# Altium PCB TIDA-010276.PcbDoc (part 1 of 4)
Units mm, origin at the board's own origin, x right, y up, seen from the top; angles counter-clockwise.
Board outline 146.48 x 90.27 mm, 4 copper layers (Top Layer, Signal Layer1, Signal Layer2, Bottom Layer), stack 1.631 mm thick; 271 components, 98 nets, 671 pads, 1828 vias.
Unrouted connection lines stored in the file: 2.
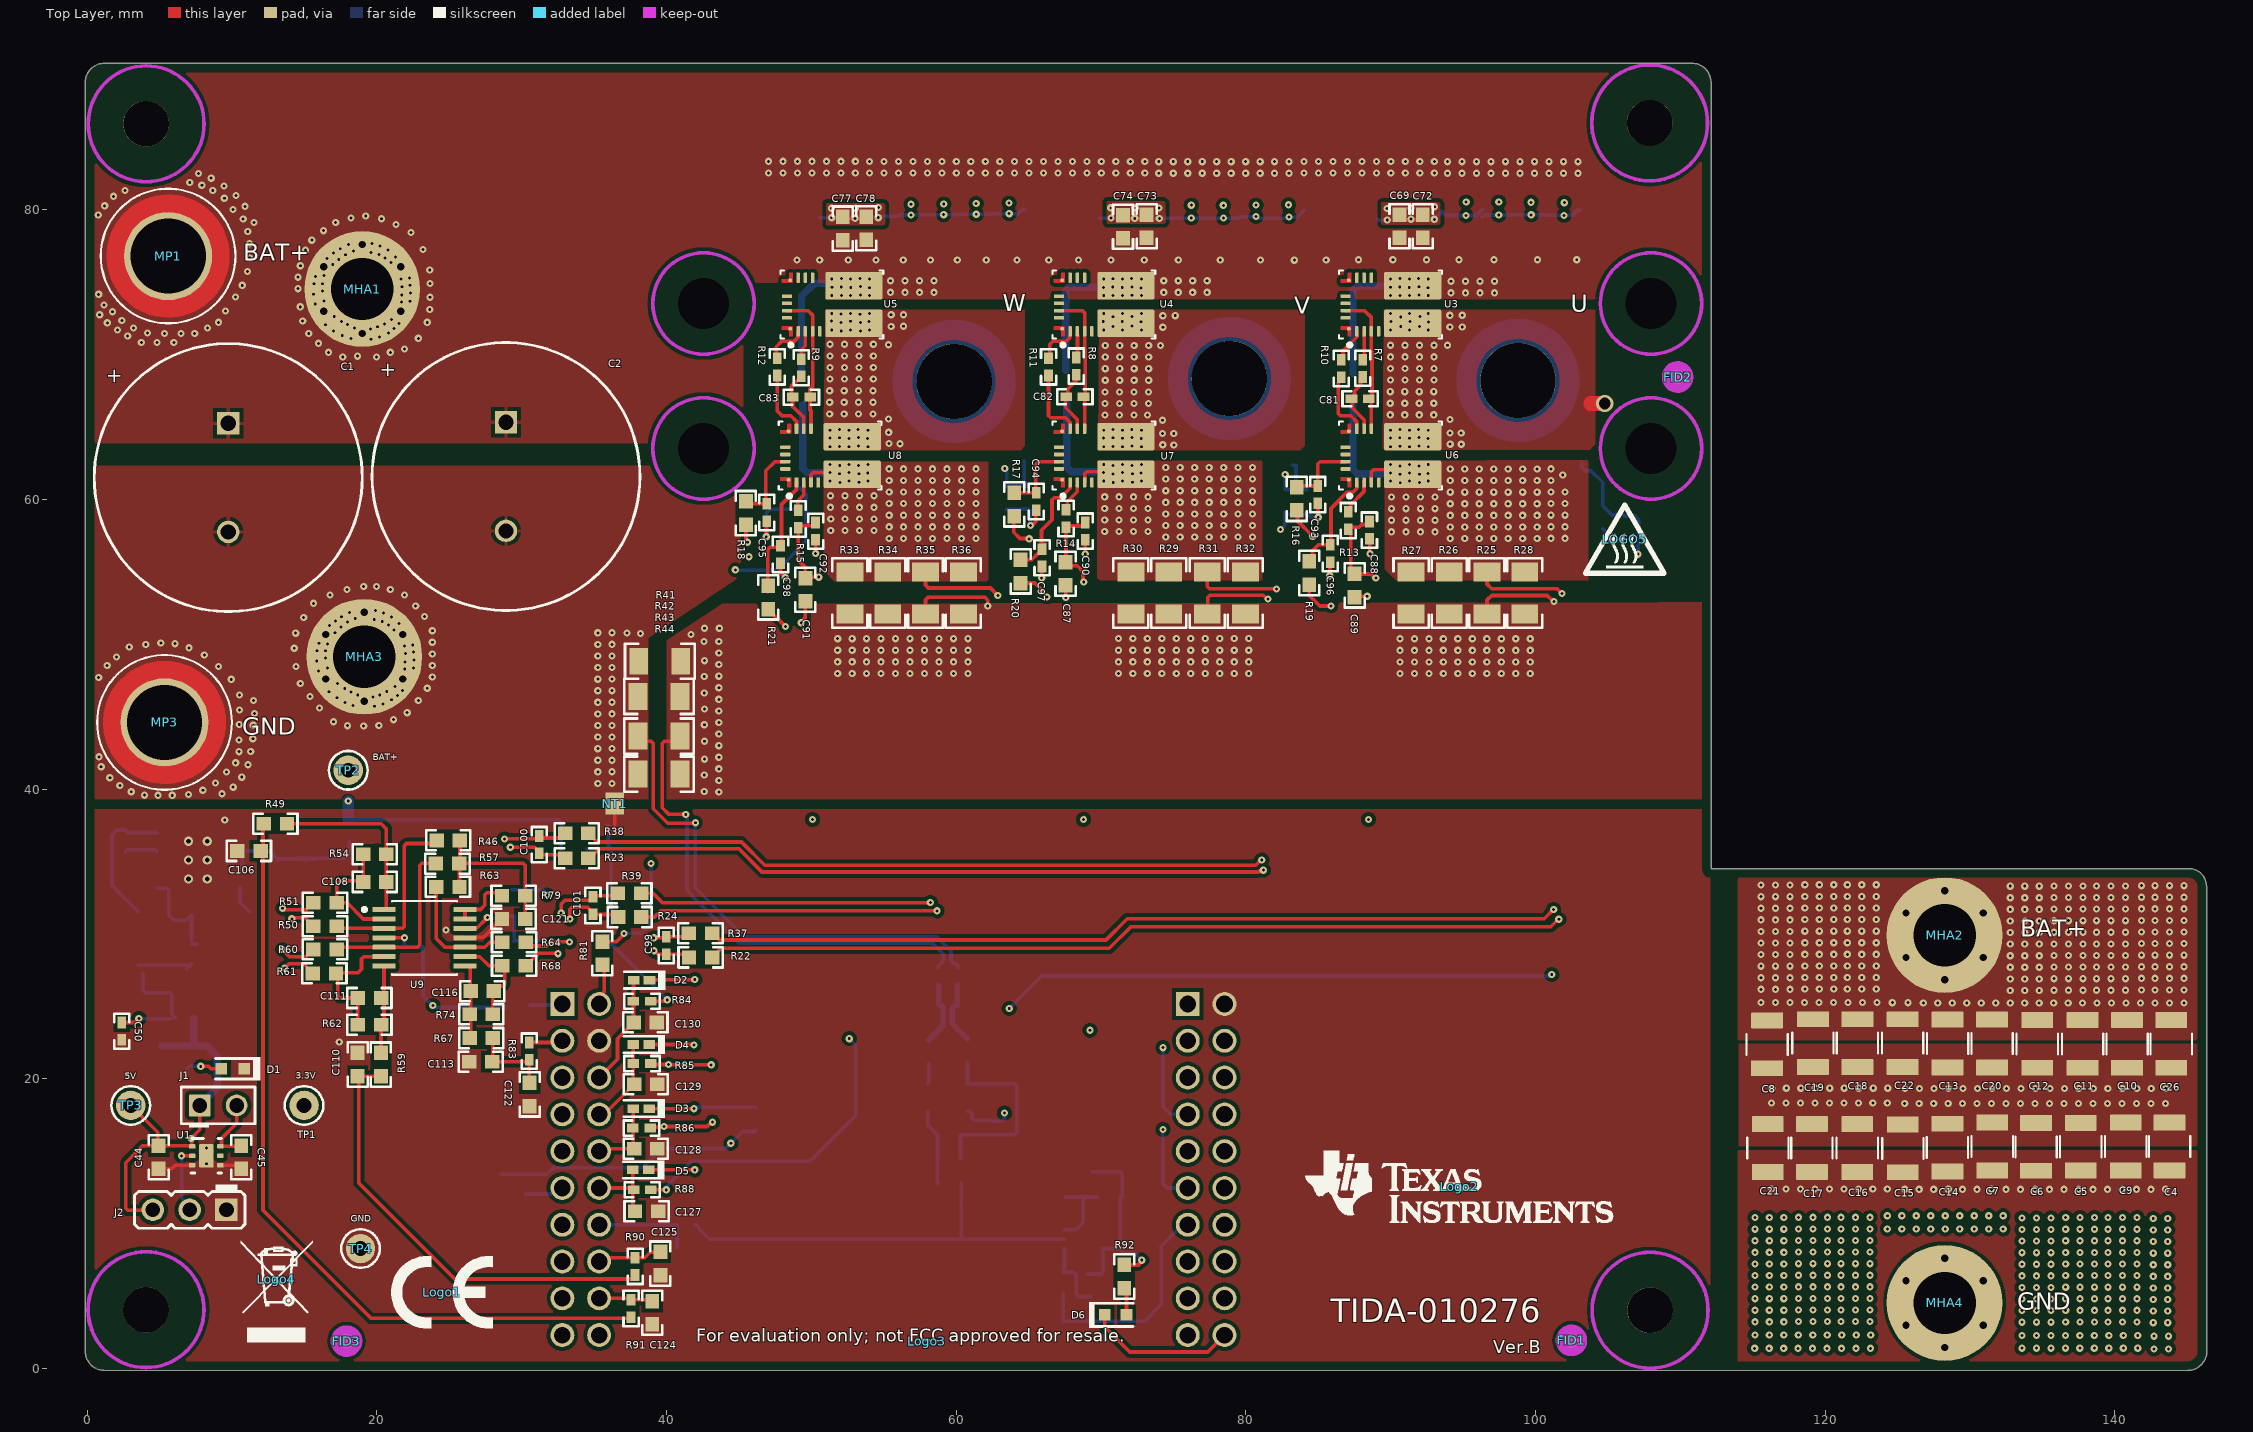
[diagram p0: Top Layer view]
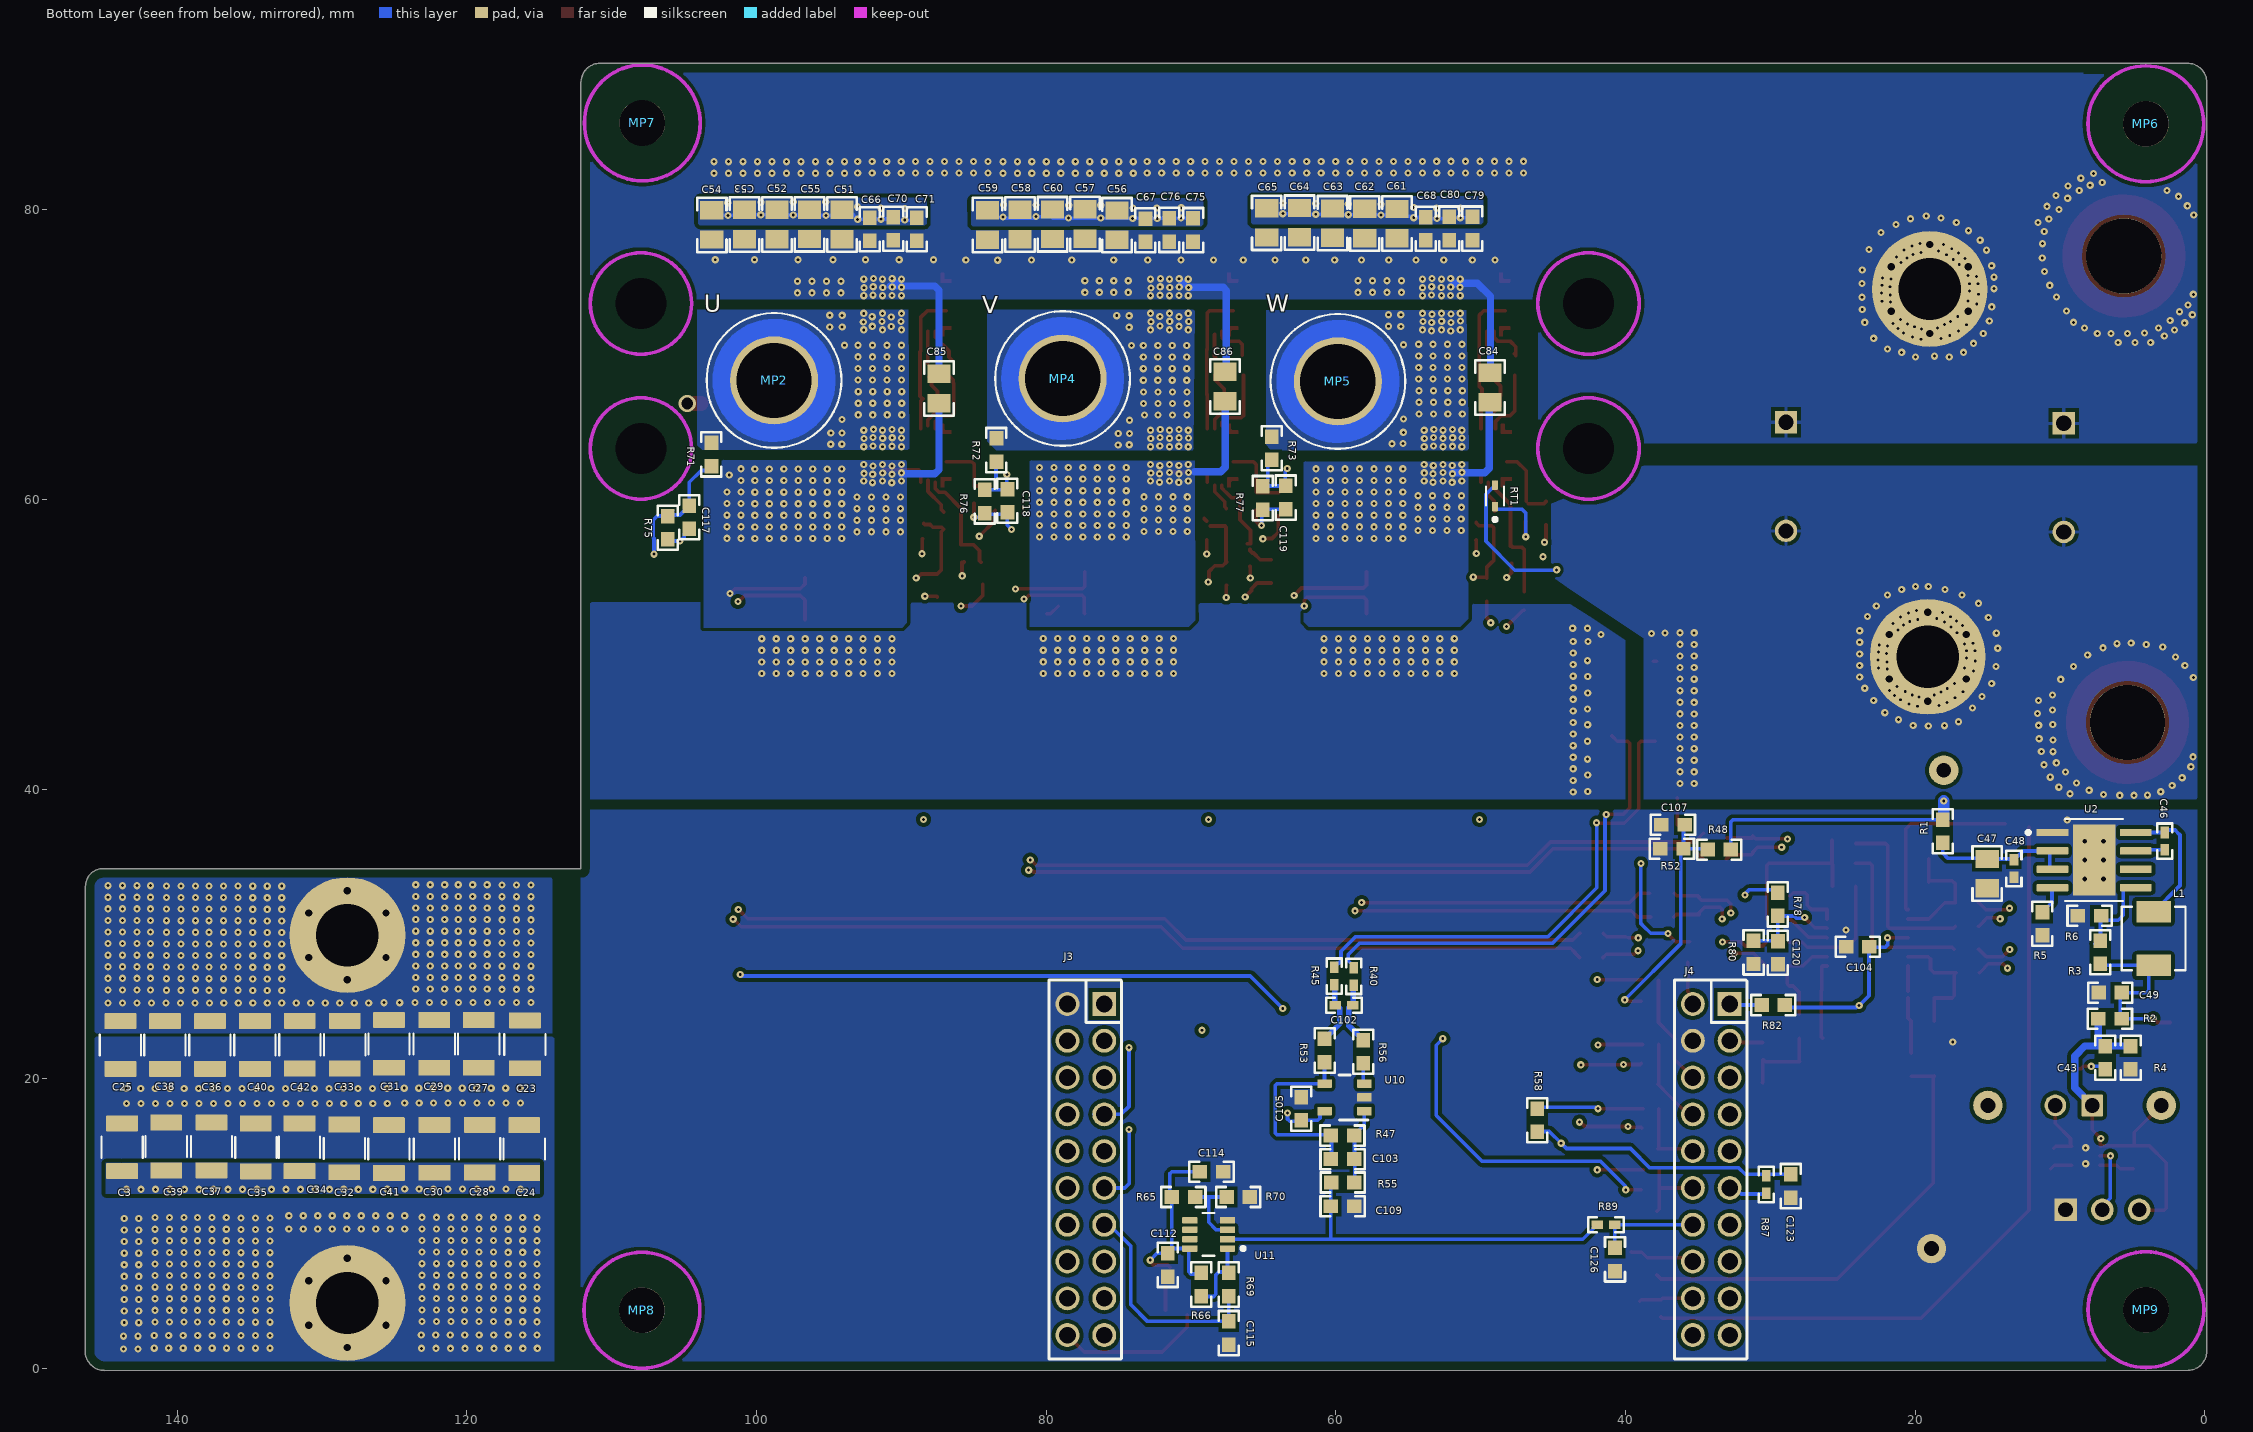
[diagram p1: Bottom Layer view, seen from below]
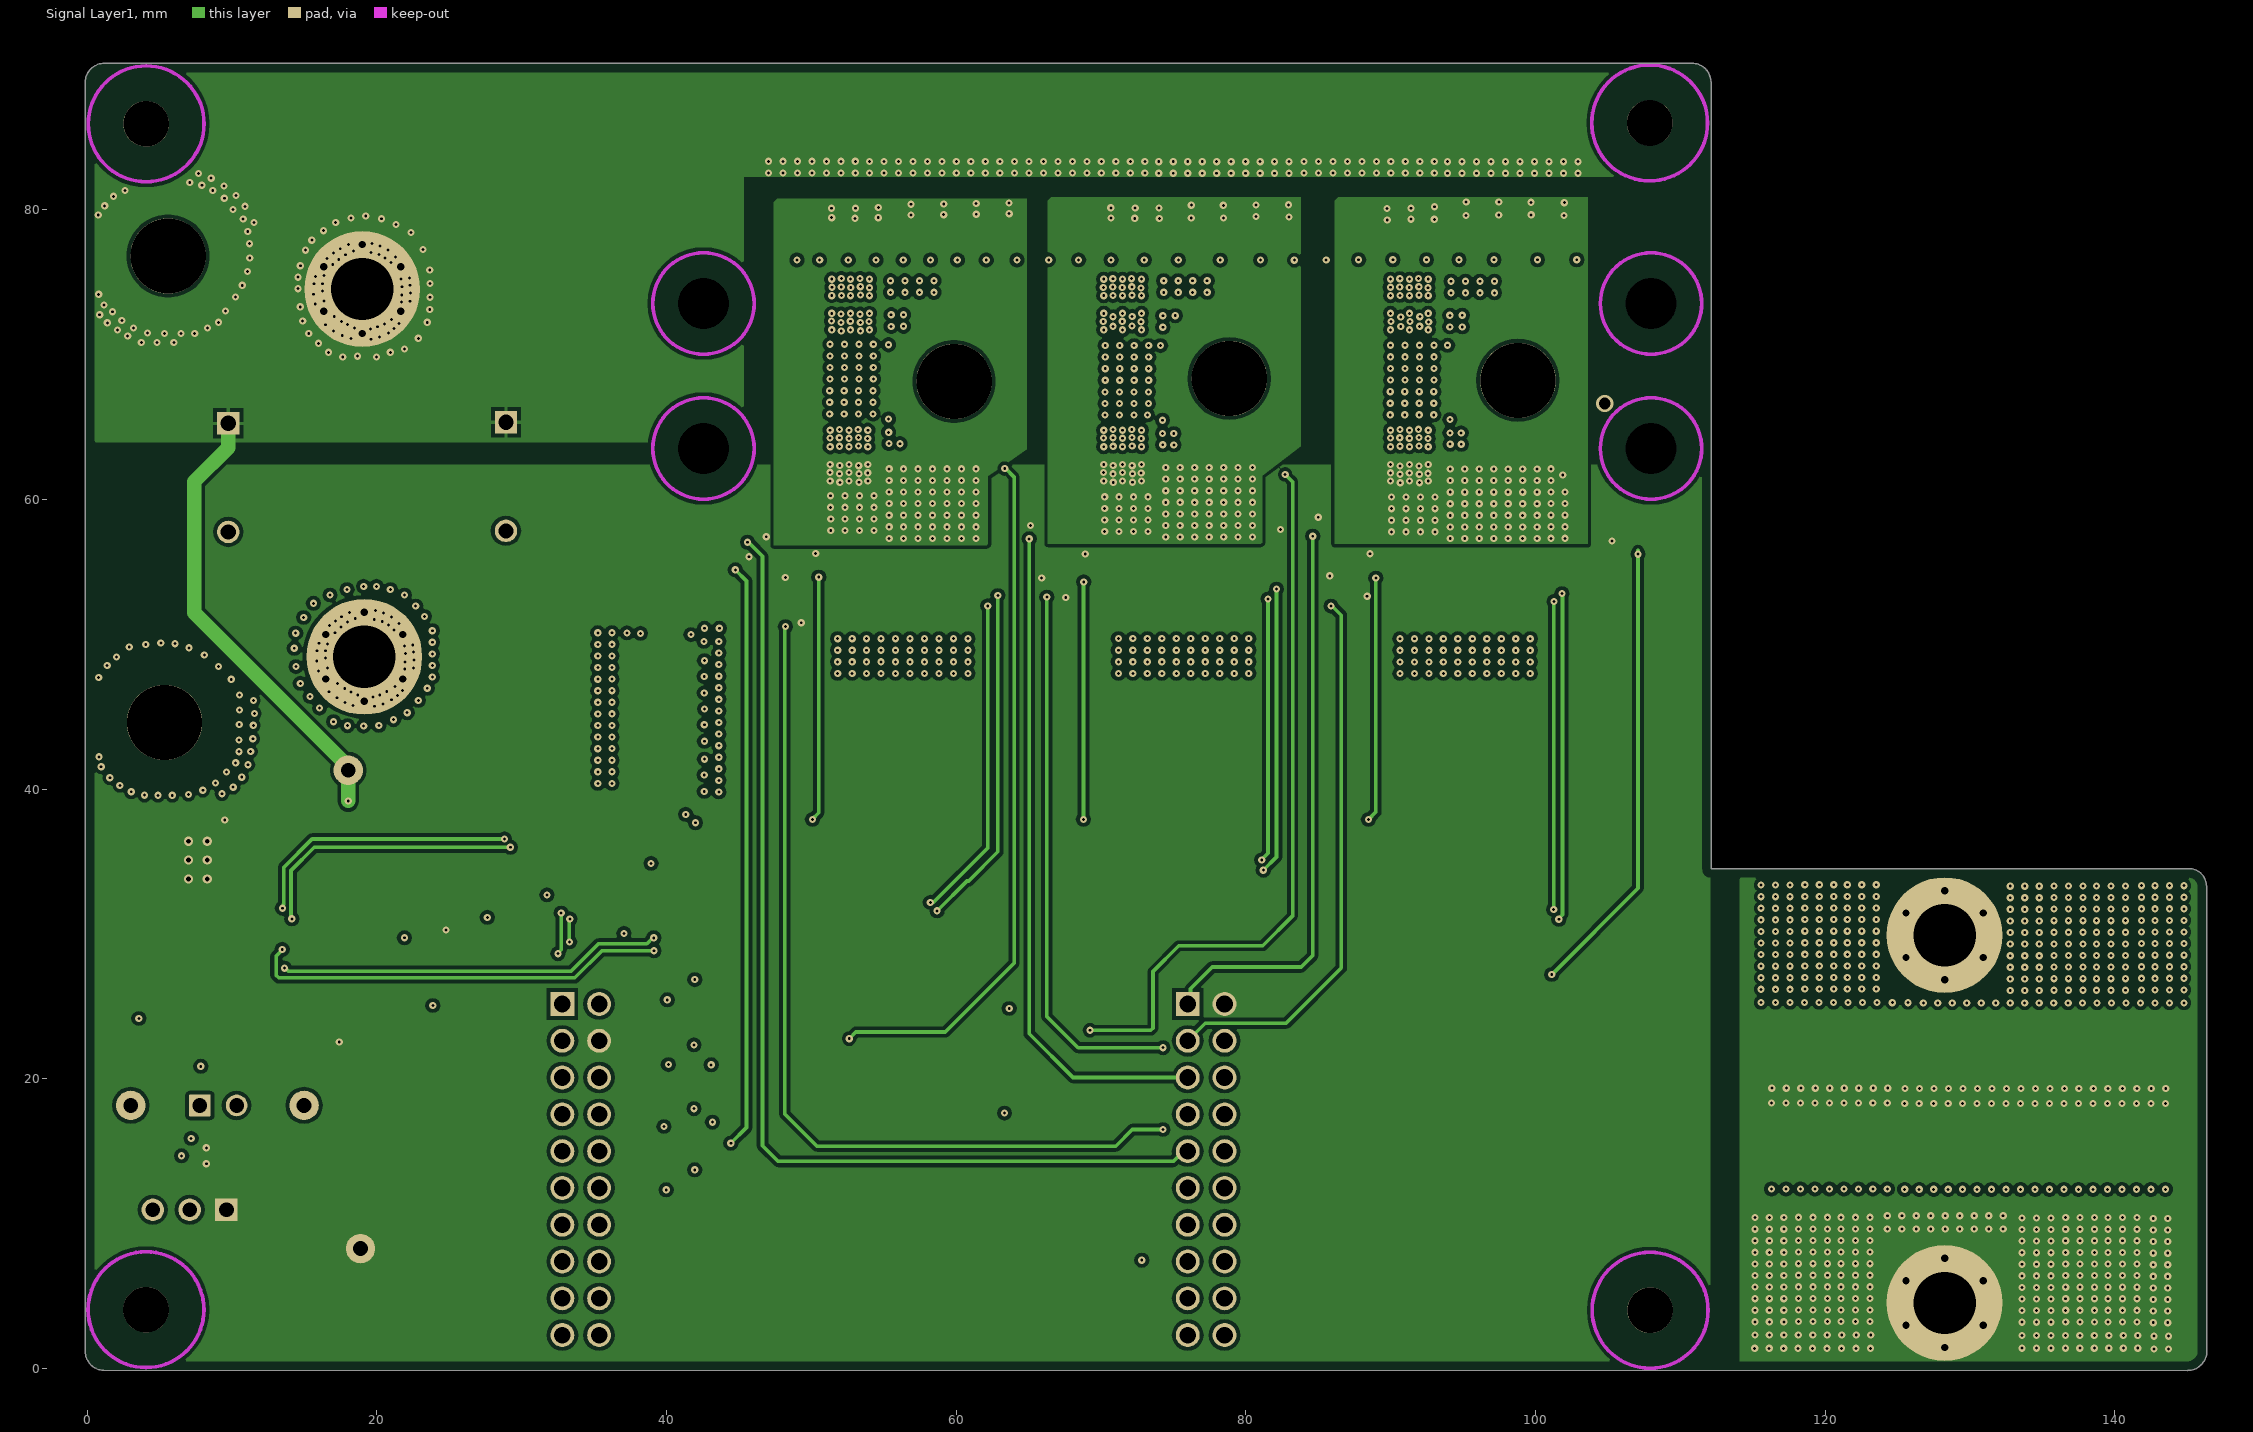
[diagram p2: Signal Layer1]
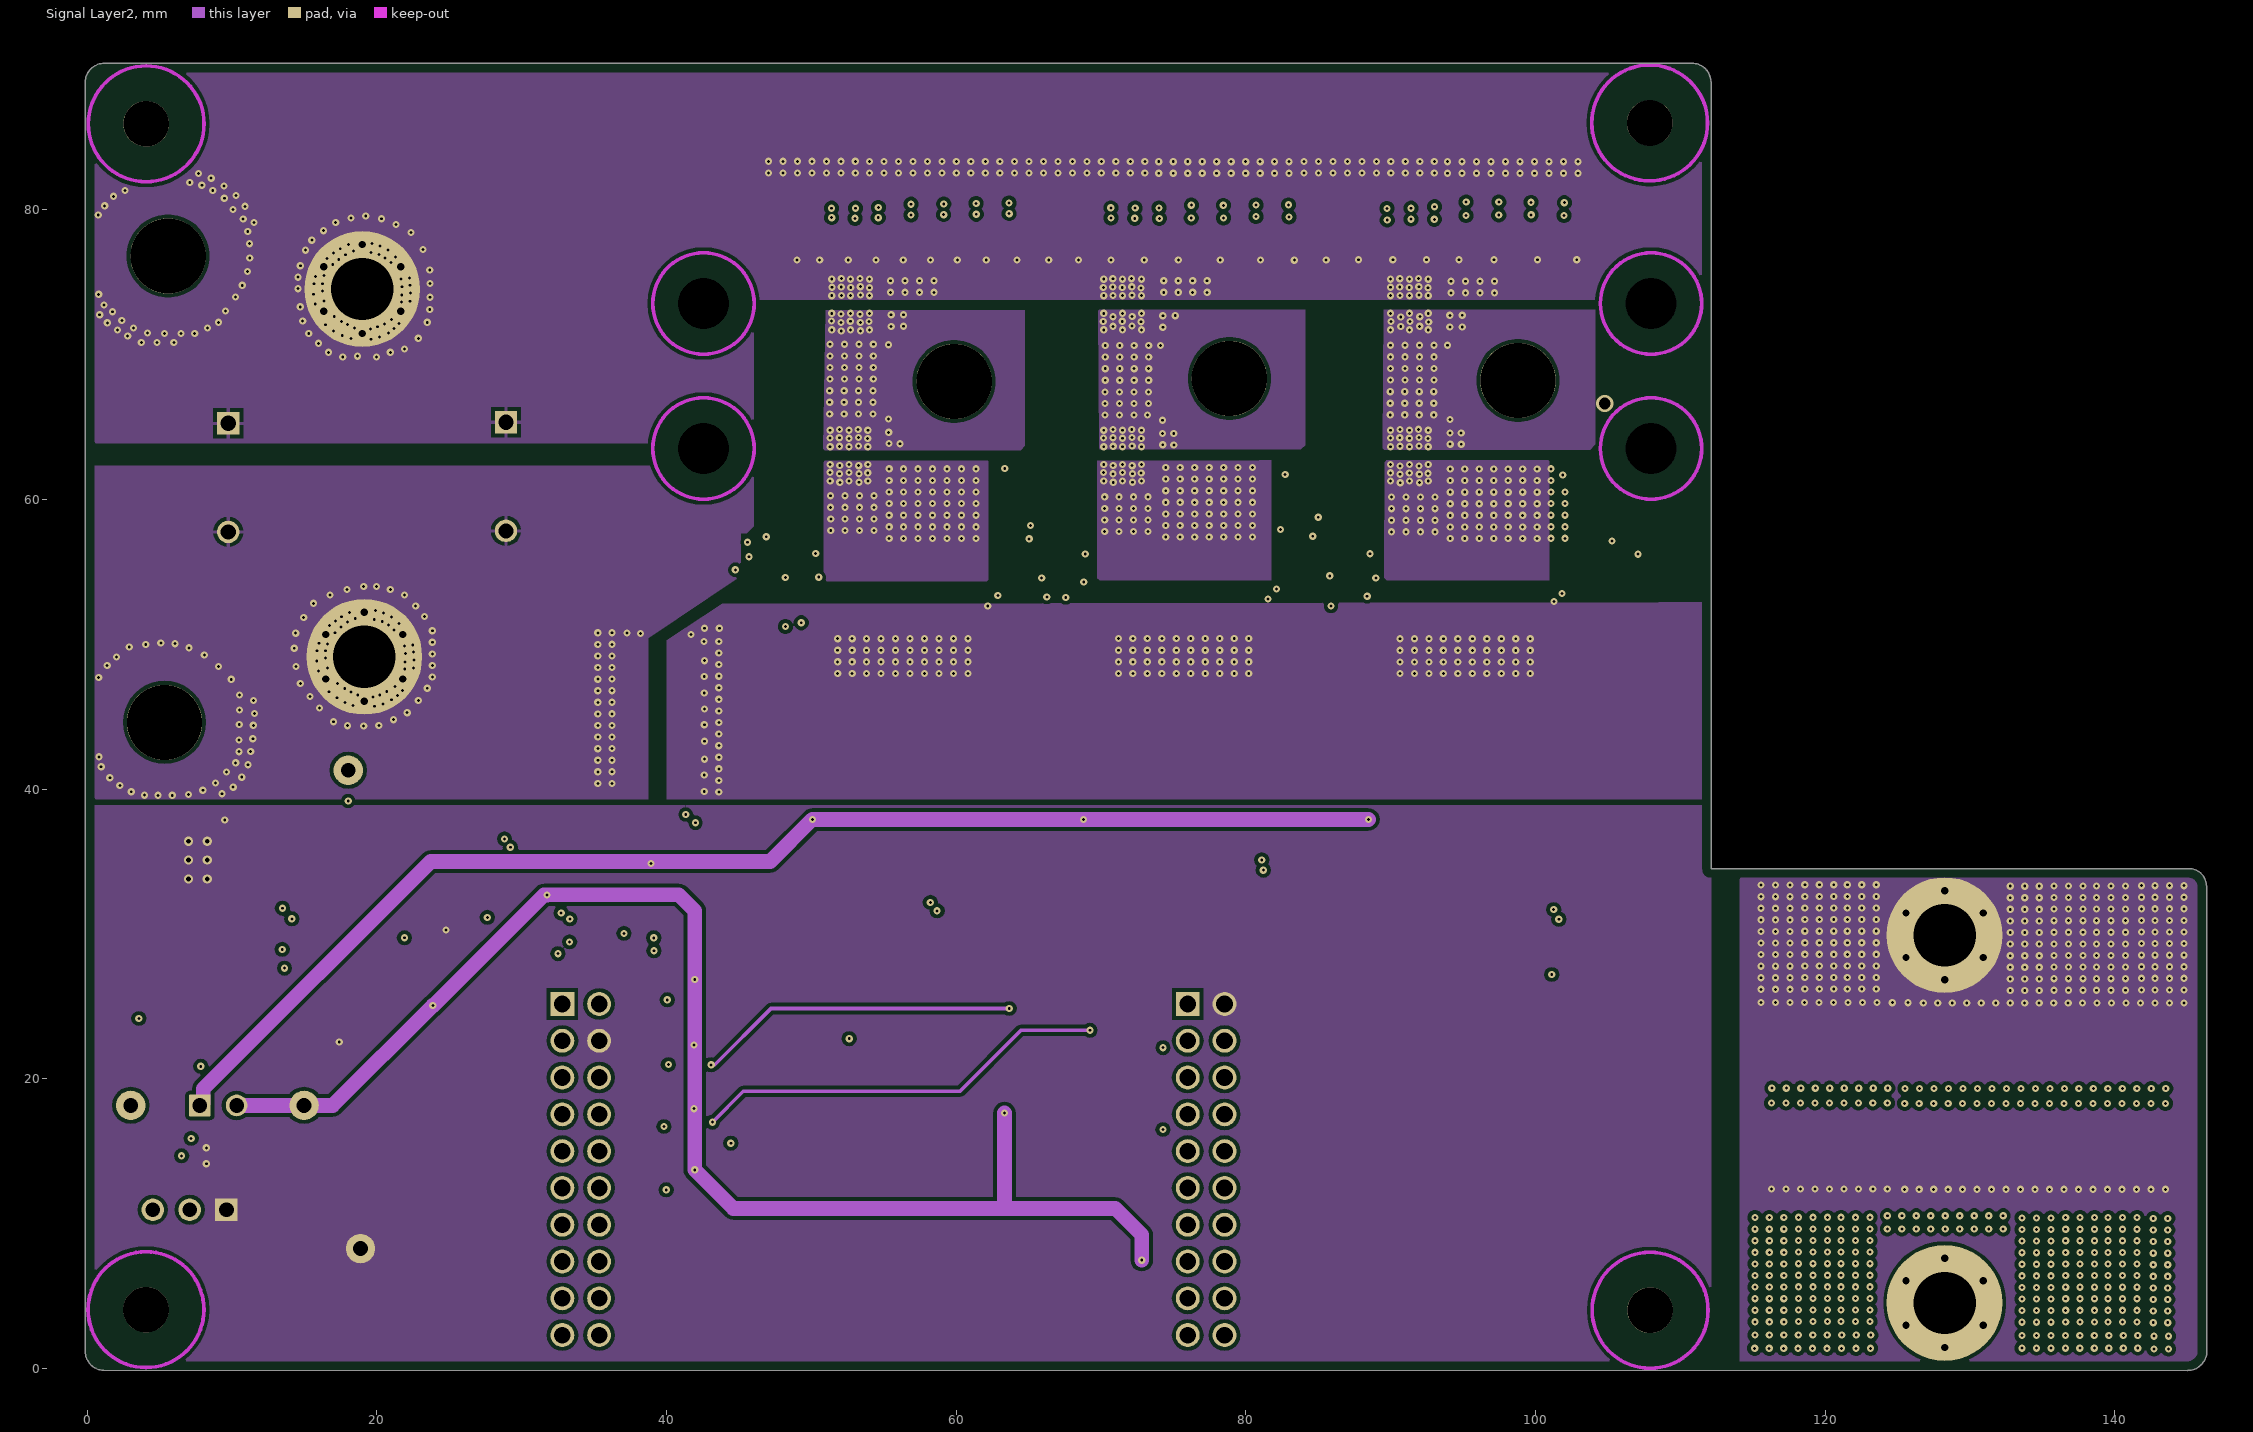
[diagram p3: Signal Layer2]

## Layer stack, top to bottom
Top Solder: solder mask 0.0102, Solder Resist, Dk 3.5
Top Layer: signal copper 0.07
Dielectric 1: prepreg 0.2032, FR-4 High Tg, Dk 4.2
Signal Layer1: signal copper 0.07
Dielectric1: core 0.9449, FR-4 High Tg, Dk 4.2
Signal Layer2: signal copper 0.07
Dielectric 2: prepreg 0.2032, FR-4 High Tg, Dk 4.2
Bottom Layer: signal copper 0.07
Bottom Solder: solder mask 0.0102, Solder Resist, Dk 3.5

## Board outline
1.138,-0.126 cw(c1.205,1.203) -0.126,1.181 -0.127,1.199 -0.127,88.804 -0.127,88.815 cw(c1.204,88.793) 1.189,90.124 1.218,90.127 110.802,90.127 110.82,90.126 cw(c110.797,88.795) 112.127,88.795 112.127,88.781 112.127,34.519 145.123,34.519 145.136,34.518 cw(c145.119,33.301) 146.336,33.301 146.336,33.288 146.355,1.194 146.355,1.193 cw(c145.024,1.199) 145.053,-0.132 145.011,-0.139

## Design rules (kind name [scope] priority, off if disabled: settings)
AcuteAngle [All] p1: minimum=4.50000000000000E+0001 checktracksonly=FALSE
AssemblyTestPointUsage [All] p1: valid=2
BoardOutlineClearance BoardOutlineClearance_MountingHoles [OnCopper and InComponentClass('Mounting Holes')] p1: gap=1 ignorepadtopadclearanceinfootprint=FALSE
BoardOutlineClearance BoardOutlineClearance_Poly [OnCopper and IsPoly] p2: gap=0.635 ignorepadtopadclearanceinfootprint=FALSE
BoardOutlineClearance [OnCopper and Not InComponentClass('Logo') and not InComponentClass('FiducialMark') and not InRegion(1000,500,4000,800) and not InPoly] p3: gap=0.5 ignorepadtopadclearanceinfootprint=FALSE
Clearance [InNet('BAT+') vs InNet('PGND')] p1 off: gap=1 ignorepadtopadclearanceinfootprint=TRUE
Clearance "Keepouts Clearance" [((IsTrack Or IsArc) And Not InPoly) And IsFree and IsKeepOut vs ((IsTrack Or IsArc) And Not InPoly) And IsFree and IsKeepOut] p2: gap=0 ignorepadtopadclearanceinfootprint=FALSE
Clearance "Poly Clearance" [InPolygon] p3: gap=0.254 ignorepadtopadclearanceinfootprint=TRUE
Clearance "FiducialMark Clearance" [IsKeepOut and InComponentClass('FiducialMark') vs IsPad and InComponentClass('FiducialMark')] p4: gap=0 ignorepadtopadclearanceinfootprint=FALSE
Clearance "ALL Clearance" [All] p5: gap=0.203 ignorepadtopadclearanceinfootprint=TRUE
ComponentClearance ComponentClearance_MountingHoles_FiducialMarks [InComponentClass('Mounting Holes') vs InComponentClass('FiducialMark')] p1: gap=1.27 collisioncheckmode=3 verticalgap=0.254 showdistances=FALSE
ComponentClearance ComponentClearance_Shunt [InComponentClass('Header') vs InComponentClass('Shunt')] p2: gap=0 collisioncheckmode=3 verticalgap=0 showdistances=FALSE
ComponentClearance ComponentClearance_Logo [InComponentClass('Logo')] p3: gap=0.762 collisioncheckmode=3 verticalgap=0.254 showdistances=FALSE
ComponentClearance ComponentClearance_ScrewToNut [(HasFootprint('NY PMS 440 0025 PH')) vs (HasFootprint('Keystone_1902C'))] p4: gap=0.127 collisioncheckmode=3 verticalgap=0.254 showdistances=FALSE
ComponentClearance ComponentClearance_MountingHoles [InComponentClass('Mounting Holes')] p5: gap=2.54 collisioncheckmode=3 verticalgap=2540 showdistances=FALSE
ComponentClearance ComponentClearance_SmallPassives [HasFootprint('0201*') or HasFootprint('0402*') or HasFootprint('0508') or HasFootprint('0603*') or HasFootprint('0612') or HasFootprint('0805*') or HasFootprint('0815*') or HasFootprint('0830*') or HasFootprint('1206*') or HasFootprint('1210*') or HasFootprint('1808*') or HasFootprint('1812*') or HasFootprint('1825*') or HasFootprint('2010*') or HasFootprint('2220*') or HasFootprint('2225*') or HasFootprint('2512*') or HasFootprint('2728*') or HasFootprint('3518*') vs HasFootprint('0201*') or HasFootprint('0402*') or HasFootprint('0508') or HasFootprint('0603*') or HasFootprint('0612') or HasFootprint('0805*') or HasFootprint('0815*') or HasFootprint('0830*') or HasFootprint('1206*') or HasFootprint('1210*') or HasFootprint('1808*') or HasFootprint('1812*') or HasFootprint('1825*') or HasFootprint('2010*') or HasFootprint('2220*') or HasFootprint('2225*') or HasFootprint('2512*') or HasFootprint('2728*') or HasFootprint('3518*')] p6: gap=0.38 collisioncheckmode=3 verticalgap=0.254 showdistances=FALSE
ComponentClearance ComponentClearance_THtoSMT [IsThruComponent vs IsSMTComponent] p7: gap=0.762 collisioncheckmode=3 verticalgap=0.762 showdistances=FALSE
ComponentClearance ComponentClearance_THtoTH [IsThruComponent vs IsThruComponent] p8: gap=0.508 collisioncheckmode=3 verticalgap=0.762 showdistances=FALSE
ComponentClearance [All] p9: gap=0.508 collisioncheckmode=3 verticalgap=0.254 showdistances=FALSE
DiffPairsRouting [All] p1: maxlimit=2.54 minlimit=0.254 mostfreqgap=0.254 toplayer_minwidth=0.381 toplayer_maxwidth=0.381 toplayer_prefwidth=0.381 midlayer1_minwidth=0.381 midlayer1_maxwidth=0.381 midlayer1_prefwidth=0.381 midlayer2_minwidth=0.381 midlayer2_maxwidth=0.381 midlayer2_prefwidth=0.381 bottomlayer_minwidth=0.381 bottomlayer_maxwidth=0.381 bottomlayer_prefwidth=0.381 maxuncoupledlength=25.4
FabricationTestPointUsage TestPointUsage [All] p1: valid=2 allowmultiple=FALSE
FabricationTestpoint Testpoint [All] p1: side=3 testpointundercomponent=TRUE minsize=1.016 maxsize=2.54 preferedsize=1.524 minholesize=0 maxholesize=1.016 preferedholesize=0.813 testpointgrid=0.025 allowsidetop=TRUE allowsidebottom=TRUE usegrid=TRUE gridtolerance=0
FanoutControl Fanout_LCC [IsLCC] p1: bgadir=Out bgaviamode=Centered fanoutstyle=Auto fanoutdirection=Alternating viagrid=0.025 // Fanout_LCC (Default Rule)
FanoutControl Fanout_BGA [IsBGA] p2: bgadir=Out bgaviamode=Centered fanoutstyle=Auto fanoutdirection=Alternating viagrid=0.025 // Fanout_BGA (Default Rule)
FanoutControl Fanout_Default [All] p4: bgadir=Out bgaviamode=Centered fanoutstyle=Auto fanoutdirection=Alternating viagrid=0.025 // Fanout_Default (Default Rule)
FanoutControl Fanout_Small [(CompPinCount < 5)] p5: bgadir=Out bgaviamode=Centered fanoutstyle=Auto fanoutdirection=OutThenIn viagrid=0.025 // Fanout_Small (Default Rule)
HoleSize [All] p1: absolutevalues=TRUE maxlimit=6.375 minlimit=0.2 maxpercent=80.000 minpercent=20.000
MinimumAnnularRing MinimumAnnularRing_ThermalPadVias [IsVia and InAnyComponent] p1: minimumring=0.15
MinimumAnnularRing [All] p2: minimumring=0.1
MinimumSolderMaskSliver MinimumSolderMaskSliver_Logo [InComponentClass('Logo') vs InComponentClass('Logo')] p1: minsoldermaskwidth=0.018
MinimumSolderMaskSliver [All] p2: minsoldermaskwidth=0.1
PlaneConnect [All] p1: planeconnectstyle=Direct reliefexpansion=0.254 reliefentries=4 reliefconductorwidth=0.254 reliefairgap=0.254
PolygonConnect [InNet('PGND')  or InNet('BAT+') vs InComponent('C1')  or InComponent('C2')] p1: connectstyle=Relief reliefconductorwidth=0.254 reliefentries=4 polygonreliefangle="90 Angle" airgapwidth=0.254
PolygonConnect PolygonConnect_1 [All] p2: connectstyle=Direct reliefconductorwidth=0.254 reliefentries=4 polygonreliefangle="90 Angle" airgapwidth=0.254
RoutingVias ThermalPadVias [IsVia and InAnyComponent] p1: holewidth=0.2 width=0.5 viastyle="Through Hole" minholewidth=0.2 minwidth=0.5 maxholewidth=0.33 maxwidth=0.6
RoutingVias [All] p2: holewidth=0.406 width=0.864 viastyle="Through Hole" minholewidth=0.2 minwidth=0.61 maxholewidth=1.016 maxwidth=1.651
SilkToBoardRegionClearance [Not ((IsComment or IsDesignator) And (Hide <> 'False')) and not InRegion(1000,500,4000,800)] p1:
SilkToSilkClearance SilkToSilkClearance_Pb-FreeLogo [(HasFootprint('Pb-Free_Overlay_Medium') OR HasFootprint('Pb-Free_Overlay_Small')) vs (HasFootprint('Pb-Free_Overlay_Medium') OR HasFootprint('Pb-Free_Overlay_Small'))] p1: silktosilkclearance=0
SilkToSilkClearance [All] p2: silktosilkclearance=0.1
SilkToSolderMaskClearance SilkToComponentPadClearance [(IsPad or IsFill or IsRegion) and InAnycomponent] p1: minsilkscreentomaskgap=0.127 clearancetoexposedcopper=TRUE
SilkToSolderMaskClearance "Silk to Solder Mask Opening" [All] p2: minsilkscreentomaskgap=0.1 clearancetoexposedcopper=FALSE
SolderMaskExpansion [All] p1: expansion=0.05 istentingtop=FALSE
UnRoutedNet [All] p1: checkbadconnections=TRUE
Width [All] p1: maxlimit=2.54 minlimit=0.152 preferedwidth=0.254 checkconnectedcopper=TRUE
14 further rules are at their usual default settings.

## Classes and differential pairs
component class Designator: C103 C104 C105 C106 C107 C108 C109 C110 C111 C112 C113 C114 C115 C116 C117 C118 C119 C120 C121 q R46 R47 R48 R49 R50 R51 R52 R53 R54 R55 R56 R57 R58 R59 R60 R61 R62 R63 R64 R65 R66 R67 R68 R69 R70 R71 R72 R73 R74 R75 R76 R77 R78 R79 R80 RT1 U9 U10 U11
component class Designator: C51 C52 C53 C54 C55 C56 C57 C58 C59 C60 C61 C62 C63 C64 C65 C66 C67 C68 C69 C70 C71 C72 C73 C74 C75 C76 C77 C78 C79 C80 C81 C82 C83 C84 C85 C86 C87 C88 C89 C90 C91 C92 C93 C94 C95 C96 C97 C98 C99 C100 C101 C102 R7 R8 R9 R10 R11 R12 R13 R14 R15 R16 R17 R18 R19 R20 R21 R22 R23 R24 R25 R26 R27 R28 R29 R30 R31 R32 R33 R34 R35 R36 R37 R38 R39 R40 R41 R42 R43 R44 R45 U3 U4 U5 U6 U7 U8
component class Designator: C1 C2 C3 C4 C5 C6 C7 C8 C9 C10 C11 C12 C13 C14 C15 C16 C17 C18 C19 C20 C21 C22 C23 C24 C25 C26 C27 C28 C29 C30 C31 C32 C33 C34 C35 C36 C37 C38 C39 C40 C41 C42 C43 C44 C45 C46 C47 C48 C49 C50 D1 J1 J2 L1 NT1 R1 R2 R3 R4 R5 R6 TP1 TP2 TP3 TP4 U1 U2
component class Designator: C122 C123 C124 C125 C126 C127 C128 C129 C130 D2 D3 D4 D5 D6 J3 J4 J7 J8 J9 MHA1 MHA2 MHA3 MHA4 MP1 MP2 MP3 MP4 MP5 R81 R82 R83 R84 R85 R86 R87 R88 R89 R90 R91 R92
component class Header: J1 J2
component class Logo: Logo2
component class Designator: FID1 FID2 FID3 Logo1 Logo2 Logo3 Logo4 LOGO5 MP6 MP7 MP8 MP9
component class FiducialMark: FID1 FID2 FID3
differential pair I_Bus: +I_Bus_P -I_Bus_N

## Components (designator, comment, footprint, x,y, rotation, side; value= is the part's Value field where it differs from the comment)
C1 "ECA-2AM102" M_1800x3550 9.751,61.511 r270 top locked value=1000uF
C2 "ECA-2AM102" M_1800x3550 28.925,61.587 r270 top locked value=1000uF
C3 "C3225X7R2A106K250AC" FP-C3225X7R2A106K250AC_1210-MFG 143.806,15.281 r90 bottom value=10µF
C4 "C3225X7R2A106K250AC" FP-C3225X7R2A106K250AC_1210-MFG 143.781,15.332 r90 top value=10µF
C5 "C3225X7R2A106K250AC" FP-C3225X7R2A106K250AC_1210-MFG 137.648,15.319 r90 top value=10µF
C6 "C3225X7R2A106K250AC" FP-C3225X7R2A106K250AC_1210-MFG 134.566,15.306 r90 top value=10µF
C7 "C3225X7R2A106K250AC" FP-C3225X7R2A106K250AC_1210-MFG 131.538,15.332 r90 top value=10µF
C8 "C3225X7R2A106K250AC" FP-C3225X7R2A106K250AC_1210-MFG 115.991,22.385 r270 top value=10µF
C9 "C3225X7R2A106K250AC" FP-C3225X7R2A106K250AC_1210-MFG 140.761,15.331 r90 top value=10µF
C10 "C3225X7R2A106K250AC" FP-C3225X7R2A106K250AC_1210-MFG 140.848,22.418 r270 top value=10µF
C11 "C3225X7R2A106K250AC" FP-C3225X7R2A106K250AC_1210-MFG 137.775,22.418 r270 top value=10µF
C12 "C3225X7R2A106K250AC" FP-C3225X7R2A106K250AC_1210-MFG 134.651,22.418 r270 top value=10µF
C13 "C3225X7R2A106K250AC" FP-C3225X7R2A106K250AC_1210-MFG 128.453,22.444 r270 top value=10µF
C14 "C3225X7R2A106K250AC" FP-C3225X7R2A106K250AC_1210-MFG 128.439,15.255 r90 top value=10µF
C15 "C3225X7R2A106K250AC" FP-C3225X7R2A106K250AC_1210-MFG 125.366,15.205 r90 top value=10µF
C16 "C3225X7R2A106K250AC" FP-C3225X7R2A106K250AC_1210-MFG 122.218,15.222 r90 top value=10µF
C17 "C3225X7R2A106K250AC" FP-C3225X7R2A106K250AC_1210-MFG 119.092,15.23 r90 top value=10µF
C18 "C3225X7R2A106K250AC" FP-C3225X7R2A106K250AC_1210-MFG 122.23,22.469 r270 top value=10µF
C19 "C3225X7R2A106K250AC" FP-C3225X7R2A106K250AC_1210-MFG 119.157,22.469 r270 top value=10µF
C20 "C3225X7R2A106K250AC" FP-C3225X7R2A106K250AC_1210-MFG 131.527,22.444 r270 top value=10µF
C21 "C3225X7R2A106K250AC" FP-C3225X7R2A106K250AC_1210-MFG 116.045,15.222 r90 top value=10µF
C22 "C3225X7R2A106K250AC" FP-C3225X7R2A106K250AC_1210-MFG 125.354,22.469 r270 top value=10µF
C23 "C3225X7R2A106K250AC" FP-C3225X7R2A106K250AC_1210-MFG 115.991,22.385 r270 bottom value=10µF
C24 "C3225X7R2A106K250AC" FP-C3225X7R2A106K250AC_1210-MFG 116.043,15.154 r90 bottom value=10µF
C25 "C3225X7R2A106K250AC" FP-C3225X7R2A106K250AC_1210-MFG 143.922,22.342 r270 bottom value=10µF
C26 "C3225X7R2A106K250AC" FP-C3225X7R2A106K250AC_1210-MFG 143.896,22.418 r270 top value=10µF
C27 "C3225X7R2A106K250AC" FP-C3225X7R2A106K250AC_1210-MFG 119.182,22.418 r270 bottom value=10µF
C28 "C3225X7R2A106K250AC" FP-C3225X7R2A106K250AC_1210-MFG 119.117,15.179 r90 bottom value=10µF
C29 "C3225X7R2A106K250AC" FP-C3225X7R2A106K250AC_1210-MFG 122.256,22.418 r270 bottom value=10µF
C30 "C3225X7R2A106K250AC" FP-C3225X7R2A106K250AC_1210-MFG 122.243,15.171 r90 bottom value=10µF
C31 "C3225X7R2A106K250AC" FP-C3225X7R2A106K250AC_1210-MFG 125.379,22.418 r270 bottom value=10µF
C32 "C3225X7R2A106K250AC" FP-C3225X7R2A106K250AC_1210-MFG 125.391,15.154 r90 bottom value=10µF
C33 "C3225X7R2A106K250AC" FP-C3225X7R2A106K250AC_1210-MFG 128.433,22.36 r270 bottom value=10µF
C34 "C3225X7R2A106K250AC" FP-C3225X7R2A106K250AC_1210-MFG 128.464,15.205 r90 bottom value=10µF
C35 "C3225X7R2A106K250AC" FP-C3225X7R2A106K250AC_1210-MFG 134.574,15.27 r90 bottom value=10µF
C36 "C3225X7R2A106K250AC" FP-C3225X7R2A106K250AC_1210-MFG 137.743,22.347 r270 bottom value=10µF
C37 "C3225X7R2A106K250AC" FP-C3225X7R2A106K250AC_1210-MFG 137.633,15.336 r90 bottom value=10µF
C38 "C3225X7R2A106K250AC" FP-C3225X7R2A106K250AC_1210-MFG 140.848,22.347 r270 bottom value=10µF
C39 "C3225X7R2A106K250AC" FP-C3225X7R2A106K250AC_1210-MFG 140.761,15.331 r90 bottom value=10µF
C40 "C3225X7R2A106K250AC" FP-C3225X7R2A106K250AC_1210-MFG 134.637,22.347 r90 bottom value=10µF
C41 "C3225X7R2A106K250AC" FP-C3225X7R2A106K250AC_1210-MFG 131.563,15.281 r270 bottom value=10µF
C42 "C3225X7R2A106K250AC" FP-C3225X7R2A106K250AC_1210-MFG 131.536,22.36 r90 bottom value=10µF
C43 "C1608X6S1C475K080AC" 0603 5.138,21.47 r270 bottom value=4.7uF
C44 "GRM185R61C105KE44D" 0603 4.943,14.595 r270 top value=1uF
C45 "C1608X6S1C475K080AC" 0603 10.648,14.595 r270 top value=4.7uF
C46 "GRM155R62A104KE14D" 0402 2.784,36.414 r90 bottom value=0.1uF
C47 "C2012X7S2A105K125AE" 0805_HV 15.035,34.169 r270 bottom value=1uF
C48 "GRM155R62A104KE14D" 0402 13.188,34.519 r270 bottom value=0.1uF
C49 "C1608X6S1C475K080AC" 0603 6.545,25.958 r0 bottom value=4.7uF
C50 "GRM155R62A104KE14D" 0402 2.396,23.293 r270 top value=0.1uF
C51 "C2012X7S2A105K125AE" 0805_HV 94.094,78.999 r90 bottom value=1uF
C52 "C2012X7S2A105K125AE" 0805_HV 98.581,78.999 r90 bottom value=1uF
C53 "C2012X7S2A105K125AE" 0805_HV 100.836,78.98 r90 bottom value=1uF
C54 "C2012X7S2A105K125AE" 0805_HV 103.092,78.968 r90 bottom value=1uF
C55 "C2012X7S2A105K125AE" 0805_HV 96.343,79.005 r90 bottom value=1uF
C56 "C2012X7S2A105K125AE" 0805_HV 75.126,78.941 r90 bottom value=1uF
C57 "C2012X7S2A105K125AE" 0805_HV 77.334,79.014 r90 bottom value=1uF
C58 "C2012X7S2A105K125AE" 0805_HV 81.808,78.986 r90 bottom value=1uF
C59 "C2012X7S2A105K125AE" 0805_HV 84.048,78.958 r90 bottom value=1uF
C60 "C2012X7S2A105K125AE" 0805_HV 79.574,79.007 r90 bottom value=1uF
C61 "C2012X7S2A105K125AE" 0805_HV 55.774,79.046 r90 bottom value=1uF
C62 "C2012X7S2A105K125AE" 0805_HV 58.012,79.068 r90 bottom value=1uF
C63 "C2012X7S2A105K125AE" 0805_HV 60.238,79.08 r90 bottom value=1uF
C64 "C2012X7S2A105K125AE" 0805_HV 62.526,79.114 r90 bottom value=1uF
C65 "C2012X7S2A105K125AE" 0805_HV 64.78,79.108 r90 bottom value=1uF
C66 "HMK107C7224KAHTE" 0603 92.18,78.657 r90 bottom value=0.22uF
C67 "HMK107C7224KAHTE" 0603 73.157,78.601 r90 bottom value=0.22uF
C68 "HMK107C7224KAHTE" 0603 53.805,78.699 r90 bottom value=0.22uF
C69 "HMK107C7224KAHTE" 0603 90.617,78.867 r90 top value=0.22uF
C70 "HMK107C7224KAHTE" 0603 90.558,78.694 r90 bottom value=0.22uF
C71 "HMK107C7224KAHTE" 0603 88.936,78.663 r90 bottom value=0.22uF
C72 "HMK107C7224KAHTE" 0603 92.222,78.878 r90 top value=0.22uF
C73 "HMK107C7224KAHTE" 0603 73.157,78.872 r90 top value=0.22uF
C74 "HMK107C7224KAHTE" 0603 71.526,78.84 r90 top value=0.22uF
C75 "HMK107C7224KAHTE" 0603 69.862,78.605 r90 bottom value=0.22uF
C76 "HMK107C7224KAHTE" 0603 71.516,78.613 r90 bottom value=0.22uF
C77 "HMK107C7224KAHTE" 0603 52.176,78.711 r90 top value=0.22uF
C78 "HMK107C7224KAHTE" 0603 53.807,78.724 r90 top value=0.22uF
C79 "HMK107C7224KAHTE" 0603 50.58,78.711 r90 bottom value=0.22uF
C80 "HMK107C7224KAHTE" 0603 52.176,78.711 r90 bottom value=0.22uF
C81 "GRM155R71H331KA01D" 0402 87.901,66.952 r0 top value=330pF
C82 "GRM155R71H331KA01D" 0402 68.199,67.105 r0 top value=330pF
C83 "GRM155R71H331KA01D" 0402 49.319,67.074 r0 top value=330pF
C84 "GRM21BR72A103KA01L" 0805_HV 49.36,67.727 r270 bottom value=0.01uF
C85 "GRM21BR72A103KA01L" 0805_HV 87.404,67.672 r270 bottom value=0.01uF
C86 "GRM21BR72A103KA01L" 0805_HV 67.653,67.81 r270 bottom value=0.01uF
C87 "GRM188Z71C225KE43" 0603 67.558,54.882 r270 top value=2.2uF
C88 "GCM155R71H104KE02D" 0402 88.544,57.884 r270 top value=0.1uF
C89 "GRM188Z71C225KE43" 0603 87.517,54.069 r270 top value=2.2uF
C90 "GCM155R71H104KE02D" 0402 68.93,57.817 r270 top value=0.1uF
C91 "GRM188Z71C225KE43" 0603 49.598,53.767 r270 top value=2.2uF
C92 "GCM155R71H104KE02D" 0402 50.302,57.813 r270 top value=0.1uF
C93 "GRM1555C1H100JA01D" 0402 84.977,60.335 r270 top value=10pF
C94 "GRM1555C1H100JA01D" 0402 65.536,59.867 r270 top value=10pF
C95 "GRM1555C1H100JA01D" 0402 46.927,59.104 r270 top value=10pF
C96 "GRM1555C1H100JA01D" 0402 85.843,56.268 r270 top value=10pF
C97 "GRM1555C1H100JA01D" 0402 65.935,55.978 r270 top value=10pF
C98 "GRM1555C1H100JA01D" 0402 47.879,56.197 r270 top value=10pF
C99 "GRM1555C1H102FA01D" 0402 39.986,29.214 r90 top value=1000pF
C100 "GRM1555C1H102FA01D" 0402 31.212,36.173 r90 top value=1000pF
C101 "GRM1555C1H102FA01D" 0402 34.93,31.98 r90 top value=1000pF
C102 "GRM1555C1H102FA01D" 0402 59.446,25.084 r0 bottom value=1000pF
C103 "GRM1885C2A100JA01D" 0603 59.543,14.461 r0 bottom value=10pF
C104 "GRM188R72A104KA35D" 0603 23.967,29.124 r180 bottom value=0.1uF
C105 "GRM188R72A104KA35D" 0603 62.387,17.94 r270 bottom value=0.1uF
C106 "GRM1885C2A101JA01D" 0603 11.178,35.739 r180 top value=100pF
C107 "GRM188R72A104KA35D" 0603 36.734,37.546 r0 bottom value=0.1uF
C108 "GRM1885C2A100JA01D" 0603 19.867,33.597 r180 top value=10pF
C109 "GRM1885C2A101JA01D" 0603 59.543,11.201 r180 bottom value=100pF
C110 "GRM1885C2A101JA01D" 0603 18.681,20.995 r90 top value=100pF
C111 "GRM1885C2A100JA01D" 0603 19.499,25.585 r180 top value=10pF
C112 "GRM188R72A104KA35D" 0603 71.617,7.156 r90 bottom value=0.1uF
C113 "GRM1885C2A101JA01D" 0603 27.18,21.177 r180 top value=100pF
C114 "GRM188R72A104KA35D" 0603 68.591,13.582 r180 bottom value=0.1uF
C115 "GRM1885C2A101JA01D" 0603 67.395,2.453 r270 bottom value=100pF
C116 "GRM1885C2A100JA01D" 0603 27.289,26.063 r0 top value=10pF
C117 "GRM188R72A104KA35D" 0603 104.643,58.779 r270 bottom value=0.1uF
C118 "GRM188R72A104KA35D" 0603 82.684,59.907 r270 bottom value=0.1uF
C119 "GRM188R72A104KA35D" 0603 63.473,60.138 r270 bottom value=0.1uF
C120 "GRM188R72A104KA35D" 0603 29.484,28.704 r270 bottom value=0.1uF
C121 "GRM1885C2A101JA01D" 0603 29.451,31.042 r180 top value=100pF
C122 "CMP-0006827-4" 0603 30.554,18.925 r270 top value=2200pF
C123 "CMP-0006827-4" 0603 28.595,12.601 r270 bottom value=2200pF
C124 "CMP-0006827-4" 0603 39.025,3.851 r270 top value=2200pF
C125 "CMP-0006827-4" 0603 39.588,7.249 r270 top value=2200pF
C126 "CMP-0006827-4" 0603 40.735,7.533 r270 bottom value=2200pF
C127 "CMP-0006827-4" 0603 38.634,10.863 r0 top value=2200pF
C128 "CMP-0006827-4" 0603 38.584,15.17 r0 top value=2200pF
C129 "CMP-0006827-4" 0603 38.582,19.624 r0 top value=2200pF
C130 "CMP-0006827-4" 0603 38.551,23.901 r0 top value=2200pF
D1 "CMP-0002905-2" WL-SMCW_GREEN 10.067,20.702 r180 top value=Green
D2 "CMP-0028644-3" SOD-523 38.285,26.815 r180 top value=70V
D3 "CMP-0028644-3" SOD-523 38.253,17.944 r180 top value=70V
D4 "CMP-0028644-3" SOD-523 38.269,22.372 r180 top value=70V
D5 "CMP-0028644-3" SOD-523 38.23,13.72 r180 top value=70V
D6 "LTST-C193KRKT-5A" LTST-C193_Red 71.018,3.708 r180 top value=Red
FID1 "Fiducial" Fiducial10-20 102.488,1.944 r0 top
FID2 "Fiducial" Fiducial10-20 109.811,68.46 r0 top
FID3 "Fiducial" Fiducial10-20 17.913,1.895 r0 top
J1 "CMP-0002337-1" CONN_PEC02SAAN 9.059,18.168 r0 top
J2 "GBC03SAAN" Sullins_Gxx03SAAN 7.084,10.962 r180 top
J3 "CMP-0075442-1" CONN_SSW-110-23-F-D 77.267,13.741 r90 bottom
J4 "CMP-0075442-1" CONN_SSW-110-23-F-D 34.087,13.741 r90 bottom locked
L1 "74437324220" WE-LHMI_4020 3.544,29.689 r270 bottom value=22uH
Logo1 "CE Mark" CE_Mark_5mm 24.504,5.268 r0 top
Logo2 "Texas Instruments" TI_Stacked_Overlay_Small 94.742,12.548 r0 top
Logo3 "FCC disclaimer" FCC_disclaimer 57.977,1.895 r0 top
Logo4 "WEEE logo" WEEE_Minimum 13.054,6.183 r0 top
LOGO5 "CAUTION HOT SURFACE" IEC_HotSurface_Small 106.167,57.27 r0 top
MHA1 "MTG_Pads_M4" MTGP_M4_Washer 19.001,74.53 r0 top
MHA2 "MTG_Pads_M4" MTGP_M4_Washer 128.254,29.921 r0 top
MHA3 "MTG_Pads_M4" MTGP_M4_Washer 19.143,49.144 r0 top
MHA4 "MTG_Pads_M4" MTGP_M4_Washer 128.254,4.535 r0 top
MP1 "746600430R" FP-746600430R_SMT_SCREW_TERMINAL_7MM0-MFG 5.598,76.813 r0 top
MP2 "746600430R" FP-746600430R_SMT_SCREW_TERMINAL_7MM0-MFG 98.793,68.225 r180 bottom
MP3 "746600430R" FP-746600430R_SMT_SCREW_TERMINAL_7MM0-MFG 5.351,44.611 r0 top
MP4 "746600430R" FP-746600430R_SMT_SCREW_TERMINAL_7MM0-MFG 78.87,68.355 r180 bottom
MP5 "746600430R" FP-746600430R_SMT_SCREW_TERMINAL_7MM0-MFG 59.864,68.154 r180 bottom
MP6 "970130365" FP-970130365_SPCAER_M3-MFG 4.082,85.94 r180 bottom
MP7 "970130365" FP-970130365_SPCAER_M3-MFG 107.886,86.001 r180 bottom
MP8 "970130365" FP-970130365_SPCAER_M3-MFG 107.918,4.026 r180 bottom
MP9 "970130365" FP-970130365_SPCAER_M3-MFG 4.072,4.07 r180 bottom
NT1 "CMP-0078142-6" Net-Tie_50milWide_30milLong 36.443,39.013 r270 top net-tie
R1 "PMR03EZPJ000" 0603 18.11,37.095 r90 bottom value=0
R2 "PMR03EZPJ000" 0603 6.56,24.155 r180 bottom value=0
R3 "CRCW0603100KJNEAC" 0603 7.228,28.746 r270 bottom value=100k
R4 "RC0603JR-071KL" 0603 6.891,21.467 r90 bottom value=1.0k
R5 "RC0603JR-0747KL" 0603 11.224,30.716 r90 bottom value=47k
R6 "RC0603FR-0724R9L" 0603 7.969,31.267 r180 bottom value=24.9
R7 "CRCW04023R01FKED" 0402 88.087,69.063 r90 top value=3.01
R8 "CRCW04023R01FKED" 0402 68.3,69.207 r90 top value=3.01
R9 "CRCW04023R01FKED" 0402 49.303,69.098 r90 top value=3.01
R10 "RC0402JR-070RL" 0402 86.593,69.044 r90 top value=0
R11 "RC0402JR-070RL" 0402 66.384,69.164 r90 top value=0
R12 "RC0402JR-070RL" 0402 47.657,69.164 r90 top value=0
R13 "CRCW04023R01FKED" 0402 87.08,58.544 r90 top value=3.01
R14 "CRCW04023R01FKED" 0402 67.591,58.695 r90 top value=3.01
R15 "CRCW04023R01FKED" 0402 49.109,58.663 r90 top value=3.01
R16 "PMR03EZPJ000" 0603 83.527,60.045 r270 top value=0
R17 "PMR03EZPJ000" 0603 64.014,59.662 r270 top value=0
R18 "PMR03EZPJ000" 0603 45.492,59.067 r270 top value=0
R19 "PMR03EZPJ000" 0603 84.384,54.929 r270 top value=0
R20 "PMR03EZPJ000" 0603 64.458,55.036 r270 top value=0
R21 "PMR03EZPJ000" 0603 47.029,53.239 r270 top value=0
R22 "PMR03EZPJ000" 0603 42.361,28.384 r180 top value=0
R23 "PMR03EZPJ000" 0603 33.81,35.238 r180 top value=0
R24 "PMR03EZPJ000" 0603 37.477,31.176 r180 top value=0
R25 "CRF1206-FZ-R002ELF" 1206 96.656,53.558 r90 top value=0.002
R26 "CRF1206-FZ-R002ELF" 1206 94.054,53.558 r90 top value=0.002
R27 "CRF1206-FZ-R002ELF" 1206 91.414,53.558 r90 top value=0.002
R28 "CRF1206-FZ-R002ELF" 1206 99.265,53.558 r90 top value=0.002
R29 "CRF1206-FZ-R002ELF" 1206 74.691,53.558 r90 top value=0.002
R30 "CRF1206-FZ-R002ELF" 1206 72.069,53.558 r90 top value=0.002
R31 "CRF1206-FZ-R002ELF" 1206 77.343,53.558 r90 top value=0.002
R32 "CRF1206-FZ-R002ELF" 1206 79.974,53.558 r90 top value=0.002
R33 "CRF1206-FZ-R002ELF" 1206 52.675,53.558 r90 top value=0.002
R34 "CRF1206-FZ-R002ELF" 1206 55.288,53.558 r90 top value=0.002
R35 "CRF1206-FZ-R002ELF" 1206 57.89,53.558 r90 top value=0.002
R36 "CRF1206-FZ-R002ELF" 1206 60.506,53.558 r90 top value=0.002
R37 "PMR03EZPJ000" 0603 42.354,30.059 r180 top value=0
R38 "PMR03EZPJ000" 0603 33.813,36.956 r180 top value=0
R39 "PMR03EZPJ000" 0603 37.451,32.816 r180 top value=0
R40 "CRCW0402100RJNED" 0402 58.763,27.079 r90 bottom value=100
R41 "CRF1206-FZ-R002ELF" 1206 39.544,48.83 r0 top value=0.002
R42 "CRF1206-FZ-R002ELF" 1206 39.489,46.403 r0 top value=0.002
R43 "CRF1206-FZ-R002ELF" 1206 39.489,43.673 r0 top value=0.002
R44 "CRF1206-FZ-R002ELF" 1206 39.489,41.048 r0 top value=0.002
R45 "CRCW0402100RJNED" 0402 60.117,27.096 r90 bottom value=100
R46 "RC0603FR-0751KL" 0603 24.947,36.467 r0 top value=51.0k
R47 "CRCW0603100KJNEAC" 0603 59.551,16.087 r180 bottom value=100k
R48 "CRCW0603100KFKEA" 0603 33.538,35.832 r180 bottom value=100k
R49 "CRCW0603100RFKEA" 0603 13.006,37.617 r180 top value=100
R50 "CRCW06031K00FKEA" 0603 16.432,30.542 r0 top value=1.00k
R51 "CRCW06031K00FKEA" 0603 16.432,32.164 r0 top value=1.00k
R52 "RC0603FR-074K22L" 0603 36.803,35.882 r180 bottom value=4.22k
R53 "CRCW06031K00FKEA" 0603 60.786,21.959 r270 bottom value=1.00k
R54 "RC0603FR-0751KL" 0603 19.867,35.516 r0 top value=51.0k
R55 "CRCW0603100RFKEA" 0603 59.527,12.847 r0 bottom value=100
R56 "CRCW06031K00FKEA" 0603 58.108,21.87 r270 bottom value=1.00k
R57 "RC0603FR-0751KL" 0603 24.886,34.865 r0 top value=51.0k
R58 "CRCW060310K0FKEA" 0603 46.095,17.141 r90 bottom value=10.0k
R59 "CRCW0603100RFKEA" 0603 20.289,20.992 r270 top value=100
R60 "CRCW06031K00FKEA" 0603 16.432,28.942 r0 top value=1.00k
R61 "CRCW06031K00FKEA" 0603 16.39,27.285 r180 top value=1.00k
R62 "RC0603FR-0751KL" 0603 19.499,23.744 r0 top value=51.0k
R63 "RC0603FR-0751KL" 0603 24.916,33.253 r0 top value=51.0k
R64 "CRCW06031K00FKEA" 0603 29.484,29.429 r180 top value=1.00k
R65 "CRCW060310K0FKEA" 0603 70.527,11.846 r0 bottom value=10.0k
R66 "CRCW060310K0JNEA" 0603 69.301,5.806 r90 bottom value=10k
R67 "CRCW0603100RFKEA" 0603 27.212,22.819 r0 top value=100
R68 "CRCW06031K00FKEA" 0603 29.484,27.804 r180 top value=1.00k
R69 "CRCW0603100RFKEA" 0603 67.395,5.806 r270 bottom value=100
R70 "CRCW06031K00FKEA" 0603 66.749,11.846 r0 bottom value=1.00k
R71 "CRCW0603100KFKEA" 0603 103.121,63.112 r90 bottom value=100k
R72 "CRCW0603100KFKEA" 0603 83.443,63.418 r90 bottom value=100k
R73 "CRCW0603100KFKEA" 0603 64.428,63.532 r90 bottom value=100k
R74 "RC0603FR-0751KL" 0603 27.222,24.457 r180 top value=51.0k
R75 "RC0603FR-074K22L" 0603 106.129,58.06 r90 bottom value=4.22k
R76 "RC0603FR-074K22L" 0603 84.252,59.869 r90 bottom value=4.22k
R77 "RC0603FR-074K22L" 0603 65.061,60.102 r90 bottom value=4.22k
R78 "CRCW060310K0FKEA" 0603 29.491,32.048 r90 bottom value=10.0k
R79 "CRCW0603100RFKEA" 0603 29.451,32.639 r0 top value=100
R80 "CRCW060310K0FKEA" 0603 31.169,28.733 r90 bottom value=10.0k
R81 "PMR03EZPJ000" 0603 35.584,28.666 r270 top value=0
R82 "PMR03EZPJ000" 0603 29.816,25.099 r180 bottom value=0
R83 "CMP-0026876-3" 0402 30.526,21.915 r270 top value=20
R84 "CMP-0026876-3" 0402 38.325,25.365 r180 top value=20
R85 "CMP-0026876-3" 0402 38.315,21.061 r180 top value=20
R86 "CMP-0026876-3" 0402 38.284,16.608 r180 top value=20
R87 "CMP-0026876-3" 0402 30.284,12.712 r90 bottom value=20
R88 "CMP-0026876-3" 0402 38.334,12.355 r180 top value=20
R89 "CMP-0026876-3" 0402 41.357,9.931 r180 bottom value=20
R90 "CMP-0026876-3" 0402 37.84,7.058 r90 top value=20
R91 "CMP-0026876-3" 0402 37.56,4.155 r90 top value=20
R92 "RC0603JR-071KL" 0603 71.617,6.356 r270 top value=1.0k
RT1 "TMP6131DYAT" DYA0002A-MFG 49.019,60.25 r90 bottom value=10k
TP1 "5000" Keystone5000 14.984,18.168 r90 top
TP2 "5000" Keystone5000 18.034,41.308 r0 top
TP3 "5000" Keystone5000 3.019,18.168 r90 top
TP4 "5000" Keystone5000 18.882,8.284 r90 top
U1 "TPS7B8133QDRVRQ1" DRV0006A 8.238,14.69 r0 top
U2 "LMR38010FDDAR" DDA0008E-MFG 7.652,35.109 r180 bottom
U3 "LMG3100R017" VBE0015A-MFG 90,73.466 r90 top locked
U4 "LMG3100R017" VBE0015A-MFG 70.2,73.466 r90 top locked
U5 "LMG3100R017" VBE0015A-MFG 51.42,73.466 r90 top locked
U6 "LMG3100R017" VBE0015A-MFG 90,63.037 r90 top locked
U7 "LMG3100R017" VBE0015A-MFG 70.2,63.037 r90 top locked
U8 "LMG3100R017" VBE0015A-MFG 51.309,63.037 r90 top locked
U9 "OPA4323" PW0014A-MFG 23.301,29.742 r0 top
U10 "LMV116MF/NOPB" DBV0005A_N 59.411,18.724 r0 bottom
U11 "LM393BIDDFR" DDF0008A-MFG 68.79,9.262 r0 bottom

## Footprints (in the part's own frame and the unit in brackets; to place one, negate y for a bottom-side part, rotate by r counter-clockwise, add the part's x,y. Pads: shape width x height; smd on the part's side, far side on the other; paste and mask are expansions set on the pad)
0402 [mm] "0402 from SM-752 data"
  rect 0.8x0.6 smd: 1(-0.6,0) 2(0.6,0)
  silkscreen extent -1.22,-0.52 1.22,0.52, body extent -0.55,-0.3 0.55,0.3, height 0.6
0603 [mm] "0603 from SM-752 data"
  rect 1x0.95 smd: 1(-0.8,0) 2(0.8,0)
  silkscreen extent -1.52,-0.69 1.52,0.69, body extent -0.87,-0.47 0.87,0.47, height 1
0805_HV [mil] "0805 with 30mil clearance between pads"
  rect 50x63 smd: 1(-40,0) 2(40,0)
  silkscreen extent -74,-40 74,40, body extent -43,-29 43,29, height 57
1206 [mm] "1206 from SM-752 data"
  rect 1.3x1.85 smd: 1(-1.45,0) 2(1.45,0)
  silkscreen extent -2.4,-1.21 2.4,1.21, body extent -1.7,-0.9 1.7,0.9, height 1.35
CE_Mark_5mm [mm] "Minimum text height for CE Mark"
  silkscreen extent -3.5,-2.5 3.5,2.5
CONN_PEC02SAAN [mm] "SULLINS"
  rrect7% 1.5x1.5 hole 1.016: 1(-1.27,0)
  round 1.5 hole 1.016: 2(1.27,0)
  silkscreen extent -2.54,-1.52 2.54,1.27, body extent -2.54,-1.27 2.54,1.27, height 8.38
CONN_SSW-110-23-F-D [mm] "SAMTEC"
  rect 1.65x1.65 hole 1.15: 1(11.43,-1.27)
  round 1.65 hole 1.15: 2(11.43,1.27) 3(8.89,-1.27) 4(8.89,1.27) 5(6.35,-1.27) 6(6.35,1.27) 7(3.81,-1.27) 8(3.81,1.27) 9(1.27,-1.27) 10(1.27,1.27) 11(-1.27,-1.27) 12(-1.27,1.27) 13(-3.81,-1.27) 14(-3.81,1.27) 15(-6.35,-1.27) 16(-6.35,1.27) 17(-8.89,-1.27) 18(-8.89,1.27) 19(-11.43,-1.27) 20(-11.43,1.27)
  silkscreen extent -13.08,-2.46 13.08,2.54, body extent -13,-2.51 13,2.54, height 8.59
DBV0005A_N [mm] "SOT23, 5-Leads, Body 2.9x1.6mm, Pitch 0.95mm, Lead Span 2.8mm, IPC Medium Density"
  rrect17% 1x0.6 smd: 1(-1.375,0.95) 2(-1.375,0) 3(-1.375,-0.95) 4(1.375,-0.95) 5(1.375,0.95)
  silkscreen extent -1.63,-1.55 0.38,1.55, body extent -1.42,-1.46 1.42,1.46, height 1.09
DDA0008E-MFG [mm]
  rrect20% 2.2x0.5 smd paste-1000 mask+0: 1(-2.875,1.905) 2(-2.875,0.635) 3(-2.875,-0.635) 4(-2.875,-1.905) 5(2.875,-1.905) 6(2.875,-0.635) 7(2.875,0.635) 8(2.875,1.905)
  rrect3% 2.95x4.9 smd paste-1000 mask-1000: 9(0,0)
  silkscreen extent -4.68,-2.83 2,2.83, body extent -3,-2.45 3,2.45, height 1.7
DDF0008A-MFG [mm]
  rrect22% 1.05x0.45 smd paste+0 mask+0: 1(-1.3,0.975) 2(-1.3,0.325) 3(-1.3,-0.325) 4(-1.3,-0.975) 5(1.3,-0.975) 6(1.3,-0.325) 7(1.3,0.325) 8(1.3,0.975)
  silkscreen extent -2.5,-1.48 0.4,1.48, body extent -1.41,-1.45 1.41,1.45, height 1.1
DRV0006A [mm] "SON, 6-Leads, Body 2x2mm, Pitch 0.65mm, Thermal Pad 1.6x1mm, TI Recommended"
  rrect33% 0.45x0.3 smd: 1(-0.975,0.65) 2(-0.975,0) 3(-0.975,-0.65) 4(0.975,-0.65) 5(0.975,0) 6(0.975,0.65)
  rrect14% 1x0.7 on Top Paste: 7(0,-0.45) 7(0,0.45)
  rrect10% 1x1.6 smd paste-0.5: 7(0,0)
  silkscreen extent -1.05,-1.2 1.05,1.2, body extent -1.05,-1.05 1.05,1.05, height 0.81
DYA0002A-MFG [mm]
  rrect25% 0.67x0.4 smd paste+0 mask+0: 1(-0.74,0) 2(0.74,0)
  silkscreen extent -1.75,-0.63 0.65,0.63, body extent -0.8,-0.39 0.8,0.39, height 0.77
FCC_disclaimer [mm]
Fiducial10-20 [mm]
  round 1 smd mask+0.5: 1(0,0)
  Top Layer keep-out circle w1.178: c0,0 r0.5
FP-746600430R_SMT_SCREW_TERMINAL_7MM0-MFG [mm]
  round 6.089 smd paste-1000 mask-1000: 1(0,0)
  round 5.2 hole 5.2 unplated paste-1000 mask+0: ""(0,0)
  Top Layer circle w1.65: c0,0 r3.425
  silkscreen extent -4.65,-4.65 4.65,4.65, body extent -4.35,-4.35 4.35,4.35, height 0.25
FP-970130365_SPCAER_M3-MFG [mm]
  round 3.15 hole 3.15 unplated paste-1000 mask+0: ""(0,0)
  body extent -3.46,-3 3.46,3, height 13.1
FP-C3225X7R2A106K250AC_1210-MFG [mm]
  rrect9% 1.1x2.2 smd paste+0 mask+0: 1(-1.65,0) 2(1.65,0)
  silkscreen extent -0.72,-1.43 0.72,1.43, body extent -1.6,-1.25 1.6,1.25, height 2.85
IEC_HotSurface_Small [mm]
  silkscreen extent -2.72,-2.36 2.72,2.35
Keystone5000 [mil] "For Keystone 500x miniature loop terminals"
  round 80 hole 40: 1(0,0)
  silkscreen extent -52,-52 52,52, body extent -49,-49 49,49, height 182
LTST-C193_Red [mm] "SMD, 2-Leads, Body1.6x0.8mm"
  rect 0.8x0.8 smd: 1(-0.75,0) 2(0.75,0)
  silkscreen extent -1.2,-0.9 1.85,0.9, body extent -0.85,-0.45 0.85,0.45, height 0.45
M_1800x3550 [mm] "TH, 2-Leads, Dia 18mm, Pin Spacing 7.5mm"
  rect 1.55x1.55 hole 1.05: 1(-3.75,0)
  round 1.55 hole 1.05: 2(3.75,0)
  silkscreen extent -9.25,-9.25 9.25,9.25, body extent -9.18,-9.23 9.22,9.24, height 37.51
MTGP_M4_Washer [mm]
  round 8 hole 4.3: 1(-0.001,0)
Net-Tie_50milWide_30milLong [mil] "50mil net tie, no solder mask opening, no solder paste"
  rect 30x50 smd paste-20 mask-20: 1(-15,0) 2(15,0)
PW0014A-MFG [mm]
  rrect29% 1.6x0.35 smd paste-1000 mask+0: 1(-2.8,1.95) 2(-2.8,1.3) 3(-2.8,0.65) 4(-2.8,0) 5(-2.8,-0.65) 6(-2.8,-1.3) 7(-2.8,-1.95) 8(2.8,-1.95) 9(2.8,-1.3) 10(2.8,-0.65) 11(2.8,0) 12(2.8,0.65) 13(2.8,1.3) 14(2.8,1.95)
  silkscreen extent -4.27,-2.55 2.25,2.55, body extent -3.7,-2.8 3.7,2.8, height 0.25
SOD-523 [mm] "NXP Semiconductor recommended land pattern, nominal STEP model"
  rect 0.8x0.6 smd paste-0.05: 1(-0.55,0) 2(0.55,0)
  silkscreen extent -1.65,-0.66 1.2,0.66, body extent -0.8,-0.4 0.8,0.4, height 0.72
Sullins_Gxx03SAAN [mm] "Header, 2.54 mm, 3x1, TH"
  rect 1.55x1.55 hole 1.016: 1(-2.54,0)
  round 1.55 hole 1.016: 2(0,0) 3(2.54,0)
  silkscreen extent -3.81,-1.75 3.81,1.27, body extent -3.81,-1.27 3.81,1.27, height 8.38
TI_Stacked_Overlay_Small [mm] "Minimum text height for CE Mark"
  silkscreen extent -10.63,-2.49 10.63,2.49
VBE0015A-MFG [mm]
  round 0.265 smd paste+0 mask-1000: 1(-1.675,2.875) 11(1.675,2.875)
  rrect40% 0.7x0.25 smd paste+0 mask-1000: 2(-1.85,2.325) 3(-1.85,1.825) 4(-1.85,1.325) 5(-1.85,0.825) 8(1.85,1.325) 9(1.85,1.825) 10(1.85,2.325)
  rrect11% 1.9x3.95 smd paste-1000 mask-1000: 6(-1.3,-1.525) 7(1.3,-1.525)
  rrect40% 0.25x0.7 smd paste+0 mask-1000: 12(0.575,3.1) 13(0.075,3.1) 14(-0.425,3.1) 15(-0.925,3.1)
  Top Layer region: 2.15,2.7 2.169,2.704 2.185,2.715 2.196,2.731 2.2,2.75 2.2,2.75 2.2,2.9 2.193,2.925 2.175,2.943 2.15,2.95 2.15,2.95 1.85,2.95 1.812,2.958 1.779,2.979 1.758,3.012 1.75,3.05 1.75,3.05 1.75,3.4 1.746,3.419 1.735,3.435 1.719,3.446 1.7,3.45 1.7,3.45 1.55,3.45 1.531,3.446 1.515,3.435 1.504,3.419 1.5,3.4 1.5,3.4 1.5,2.75 1.504,2.731 1.515,2.715 1.531,2.704 1.55,2.7 1.55,2.7
  Top Layer region: -2.15,2.7 -2.169,2.704 -2.185,2.715 -2.196,2.731 -2.2,2.75 -2.2,2.75 -2.2,2.9 -2.193,2.925 -2.175,2.943 -2.15,2.95 -2.15,2.95 -1.85,2.95 -1.812,2.958 -1.779,2.979 -1.758,3.012 -1.75,3.05 -1.75,3.05 -1.75,3.4 -1.746,3.419 -1.735,3.435 -1.719,3.446 -1.7,3.45 -1.7,3.45 -1.55,3.45 -1.531,3.446 -1.515,3.435 -1.504,3.419 -1.5,3.4 -1.5,3.4 -1.5,2.75 -1.504,2.731 -1.515,2.715 -1.531,2.704 -1.55,2.7 -1.55,2.7
  silkscreen extent -2.92,-3.55 2.35,3.55, body extent -2.35,-3.6 2.35,3.55, height 0.25
WE-LHMI_4020 [mm] "WERTH"
  rrect7% 1.5x2.4 smd: 1(-1.85,0) 2(1.85,0)
  silkscreen extent -2.2,-2.2 2.2,2.2, body extent -2.15,-2.15 2.15,2.15, height 2
WEEE_Minimum [mm] "WEEElie bin"
  silkscreen extent -2.42,-4.38 2.52,2.65
WL-SMCW_GREEN [mm] "WURTH"
  rect 0.8x0.8 smd: 1(-0.8,0) 2(0.8,0)
  silkscreen extent -1.9,-0.8 1.2,0.8, body extent -0.85,-0.45 0.85,0.45, height 0.8

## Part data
C1 C2: library part CMP-0009842-2, "CAP, AL, 1000 uF, 100 V, +/- 20%, TH", Cap_Case=18x35.5mm, Manufacturer=Panasonic, Supplier Part Number 1=P5317-ND, Tolerance_%=20%, Value1=Unknown, Value2=100V, ValueDisplayed=1000uF
C3 C4 C5 C6 C7 C8 C9 C10 C11 C12 C13 C14 C15 C16 C17 C18 C19 C20 C21 C22 C23 C24 C25 C26 C27 C28 C29 C30 C31 C32 C33 C34 C35 C36 C37 C38 C39 C40 C41 C42: library part CMP-0096021-1, "10 µF ±10% 100V Ceramic Capacitor X7R 1210 (3225 Metric)", Digikey Part Number=445-C3225X7R2A106K250ACCT-ND, Manufacturer=TDK, Mouser Part Number=810-C3225X7R2A106K25, Operating Temperature Range="-55°C to +125°C", TempCo=15%, Temperature Characteristic=X7R, Tolerance_%=10%, ValueDisplayed=10uF
C43 C45 C49: library part CMP-0007028-4, "CAP, CERM, 4.7 uF, 16 V, +/- 10%, X6S, 0603", Cap_Case=0603, Manufacturer=TDK, Supplier Part Number 1=445-9118-1-ND, TempCo=X6S, Tolerance_%=10%, Value1="0.003728 ohm", Value2=16V, ValueDisplayed=4.7uF
C44: library part CMP-0007157-5, "CAP, CERM, 1 uF, 16 V, +/- 10%, X5R, 0603", Cap_Case=0603, Manufacturer=MuRata, Supplier Part Number 1=490-3894-1-ND, TempCo=X5R, Tolerance_%=10%, Value1=Unknown, Value2=16V, ValueDisplayed=1uF
C46 C48 C50: library part CMP-0006618-1, "CAP, CERM, 0.1 uF, 100 V, +/- 10%, X5R, 0402", Cap_Case=0402, Manufacturer=MuRata, Supplier Part Number 1=490-10458-1-ND, TempCo=X5R, Tolerance_%=10%, Value1=Unknown, Value2=100V, ValueDisplayed=0.1uF
C47 C51 C52 C53 C54 C55 C56 C57 C58 C59 C60 C61 C62 C63 C64 C65: library part CMP-0750059-1, "CAP, CERM, 1 µF, 100 V,+/- 10%, X7S, 0805", Cap_Case=0805, Manufacturer=TDK, TempCo=X7S, Tolerance_%=10%, Value2=100V, ValueDisplayed=1µF
C66 C67 C68 C69 C70 C71 C72 C73 C74 C75 C76 C77 C78 C79 C80: library part CMP-0077894-3, "CAP, CERM, 0.22 µF, 100 V,+/- 10%, X7S, AEC-Q200 Grade 1, 0603", Cap_Case=0603, Manufacturer="Taiyo Yuden", Supplier Part Number 1=587-5012-1-ND, TempCo=X7S, Tolerance_%=10%, Value2=100V, ValueDisplayed=0.22µF
C81 C82 C83: library part CMP-0006687-1, "CAP, CERM, 330 pF, 50 V, +/- 10%, X7R, 0402", Cap_Case=0402, Manufacturer=MuRata, Supplier Part Number 1=490-3247-1-ND, TempCo=X7R, Tolerance_%=10%, Value1=Unknown, Value2=50V, ValueDisplayed=330pF
C84 C85 C86: library part CMP-0008361-2, "CAP, CERM, 0.01 uF, 100 V, +/- 10%, X7R, 0805", Cap_Case=0805, Manufacturer=MuRata, Supplier Part Number 1=490-1652-1-ND, TempCo=X7R, Tolerance_%=10%, Value1=Unknown, Value2=100V, ValueDisplayed=0.01uF
C87 C89 C91: library part CMP-0007499-1, "CAP, CERM, 2.2 uF, 16 V, +/- 10%, X7R, 0603", Cap_Case=0603, Manufacturer=MuRata, Supplier Part Number 1=81-GRM188Z71C225KE3D, TempCo=X7R, Tolerance_%=10%, Value1=Unknown, Value2=16V, ValueDisplayed=2.2uF
C88 C90 C92: library part CMP-0006356-2, "CAP, CERM, 0.1 uF, 50 V, +/- 10%, X7R, AEC-Q200 Grade 1, 0402", Cap_Case=0402, Manufacturer=MuRata, Supplier Part Number 1=490-10672-1-ND, TempCo=X7R, Tolerance_%=10%, Value1=Unknown, Value2=50V, ValueDisplayed=0.1uF
C93 C94 C95 C96 C97 C98: library part CMP-0006408-2, "CAP, CERM, 10 pF, 50 V, +/- 5%, C0G/NP0, 0402", Cap_Case=0402, Manufacturer=MuRata, Supplier Part Number 1=81-GRM1555C1H100JA1D, TempCo=C0G/NP0, Tolerance_%=5%, Value1=Unknown, Value2=50V, ValueDisplayed=10pF
C99 C100 C101 C102: library part CMP-0006411-2, "CAP, CERM, 1000 pF, 50 V, +/- 1%, C0G/NP0, 0402", Cap_Case=0402, Manufacturer=MuRata, Supplier Part Number 1=490-6189-1-ND, TempCo=C0G/NP0, Tolerance_%=1%, Value1=Unknown, Value2=50V, ValueDisplayed=1000pF
C103 C108 C111 C116: library part CMP-0007236-3, "CAP, CERM, 10 pF, 100 V, +/- 5%, C0G/NP0, 0603", Cap_Case=0603, Manufacturer=MuRata, Supplier Part Number 1=GRM1885C2A100JA01D-ND, TempCo=C0G/NP0, Tolerance_%=5%, Value1=Unknown, Value2=100V, ValueDisplayed=10pF
C104 C105 C107 C112 C114 C117 C118 C119 C120: library part CMP-0007469-4, "CAP, CERM, 0.1 uF, 100 V, +/- 10%, X7R, 0603", Cap_Case=0603, Manufacturer=MuRata, Supplier Part Number 1=490-3285-1-ND, TempCo=X7R, Tolerance_%=10%, Value1=Unknown, Value2=100V, ValueDisplayed=0.1uF
C106 C109 C110 C113 C115 C121: library part CMP-0007237-4, "CAP, CERM, 100 pF, 100 V, +/- 5%, C0G/NP0, 0603", Cap_Case=0603, Manufacturer=MuRata, Supplier Part Number 1=490-1351-1-ND, TempCo=C0G/NP0, Tolerance_%=5%, Value1=Unknown, Value2=100V, ValueDisplayed=100pF
C122 C123 C124 C125 C126 C127 C128 C129 C130: "CAP, CERM, 2200 pF, 16 V, +/- 10%, X7R, 0603", Cap_Case=0603, Manufacturer="Wurth Elektronik", PartNumber=885012206036, Supplier Part Number 1=710-885012206036, TempCo=X7R, Tolerance_%=10%, Value1=Unknown, Value2=16V, ValueDisplayed=2200pF
D1: "LED, Green, SMD", Color=Green, Manufacturer="Wurth Elektronik", PartNumber=150060GS75000, Value1=W, Value2=3.2V
D2 D3 D4 D5: "Diode, Schottky, 70 V, 0.07 A, SOD-523", Manufacturer=Nexperia, PartNumber=1PS79SB70,115, Value1=0.07A, Value2=0.41V
D6: library part CMP-0079922-3, "LED, Red, SMD", Color=Red, Manufacturer=Lite-On, Value1=W, Value2=2V
FID1 FID2 FID3: library part CMP-0077181-1, "Fiducial mark.  There is nothing to buy or mount.", Manufacturer=N/A
J1: "Header, 100mil, 2x1, Tin, TH", Color=Black, Current_A=3A, Manufacturer="Sullins Connector Solutions", PartNumber=PEC02SAAN, Supplier Part Number 1=S1012E-02-ND, Voltage_V=1.8kV
J2: library part CMP-0054577-1, "Header, 2.54 mm, 3x1, Gold, TH", Manufacturer="Sullins Connector Solutions"
J3 J4: "Connector, Receptacle, 100mil, 10x2, Gold plated, TH", Manufacturer=Samtec, PartNumber=SSW-110-23-F-D
L1: library part CMP-0064489-2, "Inductor, Shielded Drum Core, Powdered Iron, 22 uH, 1 A, 0.47 ohm, SMD", Manufacturer="Wurth Elektronik", Supplier Part Number 1=732-3340-1-ND, Value1="0.47 ohm", Value2=1A, ValueDisplayed=22uH
Logo1: library part CMP-0074844-1
Logo2: library part CMP-0074838-1, "Texas Instrument Corporate Signature"
Logo3: library part CMP-0074847-1, "FCC_disclaimer"
Logo4: library part CMP-0074769-1
LOGO5: library part CMP-0074837-1, "IEC 61010-1 Hot Surface Warning"
MHA1 MHA2 MHA3 MHA4: library part CMP-00001-2, "PCB Mounting Hole for M4", Manufacturer=Any, PartNumber=N/A
MP1 MP2 MP3 MP4 MP5: library part CMP-0094777-1, "Pin Screw Terminal, Power Tap M4 Surface Mount", Digikey Part Number=732-10899-1-ND, Manufacturer="Wurth Electronics", Mouser Part Number=710-746600430R, Operating Temperature Range="-55°C to +150°C"
MP6 MP7 MP8 MP9: library part CMP-0087151-1, Manufacturer="Wurth Electronics"
NT1: "Single point connection between nets.", Manufacturer=N/A
R1 R2 R16 R17 R18 R19 R20 R21 R22 R23 R24 R37 R38 R39 R81 R82: library part CMP-0086358-1, "RES, 0, 0%, 0.25 W, AEC-Q200 Grade 0, 0603", Manufacturer=Rohm, Power_W=250mW, Tolerance_%=0%, Value2=0.25W, Value_Code=0000, ValueDisplayed=0
R3 R47: library part CMP-0082530-1, "RES, 100 k, 5%, 0.1 W, 0603", Manufacturer=Vishay-Dale, Power_W=100mW, Supplier Part Number 1=541-3992-1-ND, TempCo="200 ppm/C", Tolerance_%=5%, Value2=0.1W, Value_Code=100k
R4 R92: library part CMP-0025899-5, "RES, 1.0 k, 5%, 0.1 W, 0603", Manufacturer=Yageo, Power_W=100mW, Supplier Part Number 1=311-1.0KGRCT-ND, TempCo="100 ppm/C", Tolerance_%=5%, Value2=0.1W, Value_Code=1k00, ValueDisplayed=1.0k
R5: library part CMP-0025925-5, "RES, 47 k, 5%, 0.1 W, 0603", Manufacturer=Yageo, Power_W=100mW, Supplier Part Number 1=311-47KGRCT-ND, TempCo="100 ppm/C", Tolerance_%=5%, Value2=0.1W, Value_Code=47k0, ValueDisplayed=47k
R6: library part CMP-0022947-4, "RES, 24.9, 1%, 0.1 W, 0603", Manufacturer=Yageo, Power_W=100mW, Supplier Part Number 1=311-24.9HRCT-ND, TempCo="100 ppm/C", Tolerance_%=1%, Value2=0.1W, Value_Code=24R9, ValueDisplayed=24.9
R7 R8 R9 R13 R14 R15: library part CMP-0026353-2, "RES, 3.01, 1%, 0.063 W, AEC-Q200 Grade 0, 0402", Manufacturer=Vishay-Dale, Power_W=63mW, Supplier Part Number 1=541-3.01LLCT-ND, TempCo="100 ppm/C", Tolerance_%=1%, Value2=0.063W, Value_Code=3R01, ValueDisplayed=3.01
R10 R11 R12: library part CMP-0027004-2, "RES, 0, 5%, 0.063 W, 0402", Manufacturer="Yageo America", Power_W=63mW, Supplier Part Number 1=311-0.0JRCT-ND, TempCo="200 ppm/C", Tolerance_%=5%, Value2=0.063W, Value_Code=0000, ValueDisplayed=0
R25 R26 R27 R28 R29 R30 R31 R32 R33 R34 R35 R36 R41 R42 R43 R44: library part CMP-0078822-1, "RES, 0.002, 1%, 1 W, AEC-Q200 Grade 0, 1206", Manufacturer=Bourns, Power_W=1W, Supplier Part Number 1=CRF1206-FZ-R002ELFCT-ND, TempCo="50 ppm/C", Tolerance_%=1%, Value_Code=2L000, ValueDisplayed=0.002
R40 R45: library part CMP-0026824-3, "RES, 100, 5%, 0.063 W, AEC-Q200 Grade 0, 0402", Manufacturer=Vishay-Dale, Power_W=63mW, Supplier Part Number 1=541-100JCT-ND, TempCo="200 ppm/C", Tolerance_%=5%, Value2=0.063W, Value_Code=100R, ValueDisplayed=100
R46 R54 R57 R62 R63 R74: library part CMP-0023167-5, "RES, 51.0 k, 1%, 0.1 W, 0603", Manufacturer=Yageo, Power_W=100mW, Supplier Part Number 1=311-51.0KHRCT-ND, TempCo="100 ppm/C", Tolerance_%=1%, Value2=0.1W, Value_Code=51k0, ValueDisplayed=51.0k
R48 R71 R72 R73: library part CMP-0021990-1, "RES, 100 k, 1%, 0.1 W, 0603", Manufacturer=Vishay-Dale, Power_W=100mW, Supplier Part Number 1=541-100KHCT-ND, TempCo="100 ppm/C", Tolerance_%=1%, Value2=0.1W, Value_Code=100k
R49 R55 R59 R67 R69 R79: library part CMP-0021991-4, "RES, 100, 1%, 0.1 W, AEC-Q200 Grade 0, 0603", Manufacturer=Vishay-Dale, Power_W=100mW, Supplier Part Number 1=541-100HCT-ND, TempCo="100 ppm/C", Tolerance_%=1%, Value2=0.1W, Value_Code=100R, ValueDisplayed=100
R50 R51 R53 R56 R60 R61 R64 R68 R70: library part CMP-0022109-2, "RES, 1.00 k, 1%, 0.1 W, 0603", Manufacturer=Vishay-Dale, Power_W=100mW, Supplier Part Number 1=541-1.00KHCT-ND, TempCo="100 ppm/C", Tolerance_%=1%, Value2=0.1W, Value_Code=1k00, ValueDisplayed=1.00k
R52 R75 R76 R77: library part CMP-0023146-5, "RES, 4.22 k, 1%, 0.1 W, 0603", Manufacturer=Yageo, Power_W=100mW, Supplier Part Number 1=311-4.22KHRCT-ND, TempCo="100 ppm/C", Tolerance_%=1%, Value2=0.1W, Value_Code=4k22, ValueDisplayed=4.22k
R58 R65 R78 R80: library part CMP-0021998-2, "RES, 10.0 k, 1%, 0.1 W, 0603", Manufacturer=Vishay-Dale, Power_W=100mW, Supplier Part Number 1=541-10.0KHCT-ND, TempCo="100 ppm/C", Tolerance_%=1%, Value2=0.1W, Value_Code=10k0, ValueDisplayed=10.0k
R66: library part CMP-0025701-4, "RES, 10 k, 5%, 0.1 W, AEC-Q200 Grade 0, 0603", Manufacturer=Vishay-Dale, Power_W=100mW, Supplier Part Number 1=541-10KGCT-ND, TempCo="200 ppm/C", Tolerance_%=5%, Value2=0.1W, Value_Code=10k0, ValueDisplayed=10k
R83 R84 R85 R86 R87 R88 R89 R90 R91: "RES, 20, 5%, 0.063 W, AEC-Q200 Grade 0, 0402", Manufacturer=Vishay-Dale, PartNumber=CRCW040220R0JNED, Power_W=63mW, Supplier Part Number 1=541-20JCT-ND, TempCo="200 ppm/C", Tolerance_%=5%, Value2=0.063W, Value_Code=20R0, ValueDisplayed=20
RT1: library part CMP-0091865-2, "±1% tolerance 10kΩ linear thermistor available in 0402 and 0603 package options 2-SOT-5X3 -40 to 125", Digikey Part Number=296-TMP6131DYATCT-ND, Manufacturer="Texas Instruments", Max Current=400uA, Mouser Part Number=595-TMP6131DYAT, Operating Temperature Range="-40°C to +125°C", TempCo=6400ppm/°C, Tolerance_%=1%
TP1 TP2 TP3 TP4: library part CMP-0055137-1, "Test Point, Miniature, Red, TH", Color=Red, Manufacturer=Keystone, Supplier Part Number 1=36-5000-ND
U1: library part CMP-0860463-2, "Automotive 150-mA high-voltage ultra-low-IQ low-dropout (LDO) linear regulator, DRV0006A (WSON-6)", Alternate Manufacturer="Texas Instruments", Operating Temperature Range="-40 to 150 C", Rating=Automotive
U2: library part CMP-0096892-1, "4.2-V to 80-V, 1-A Synchronous Buck Converter with 40-µA IQ", Manufacturer="Texas Instruments", Max Supply Voltage=80V, Min Supply Voltage=4.2V, Mouser Part Number=595-LMR38010FDDAR, Nominal Supply Current=40uA, Operating Temperature Range="-40°C to +150°C", Output Voltage=1-75V, Switching Frequency=200-2200kHz
U3 U4 U5 U6 U7 U8: library part CMP-0037654-1, "100-V, 64-A GaN with Integrated Driver", Manufacturer="Texas Instruments", Max Supply Voltage=5.25V, Min Supply Voltage=4.75V, Nominal Supply Current=3mA, Operating Temperature Range="-40°C to +125°C"
U9: library part CMP-0121081-1, "20 MHz High Bandwidth, 100 dB CMRR, Low Voltage (1.7 V to 5.5 V), RRIO Zero-Cross Operational Amplifier", Input Bias Current=0.0000005uA, Input Offset Voltage=0.15mV, Manufacturer="Texas Instruments", Max Dual Supply Voltage=2.75V, Max Supply Voltage=5.5V, Min Dual Supply Voltage=850mV, Min Supply Voltage=1.7V, Nominal Supply Current=1.6mA, Operating Temperature Range="-40°C to +125°C", Output Current Per Channel=110mA, Voltage Gain=120dB
U10: library part CMP-0068461-2, "Low Voltage, 45MHz, Rail-to-Rail Output Operational Amplifiers with Shutdown Option, DBV0005A (SOT-23-5)", Manufacturer="Texas Instruments", Operating Temperature Range="-40 to 85 C", Rating=Catalog
U11: library part CMP-0089113-1, "Dual Comparator SOT23-8", Input Bias Current=-0.0035uA, Input Offset Voltage=0.37mV, Manufacturer="Texas Instruments", Max Supply Voltage=36V, Min Supply Voltage=3V, Nominal Supply Current=400-550uA, Operating Temperature Range="-40°C to +85°C", Output Current Per Channel=21mA, Voltage Gain=200V/mV

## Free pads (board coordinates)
  round 1.524 hole 3.5: ""(42.562,63.525) ""(42.562,73.536) ""(107.987,63.525) ""(107.987,73.536)

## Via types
v1: diameter 0.5, hole 0.2, Top Layer to Bottom Layer, tented both sides, 1031 vias
v2: diameter 0.5, hole 0.2, Top Layer to Bottom Layer, 766 vias
v3: diameter 1, hole 0.5, Top Layer to Bottom Layer, 24 vias
v4: diameter 0.63, hole 0.33, Top Layer to Bottom Layer, tented both sides, 6 vias
v5: diameter 1.2, hole 0.8, Top Layer to Bottom Layer, 1 vias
